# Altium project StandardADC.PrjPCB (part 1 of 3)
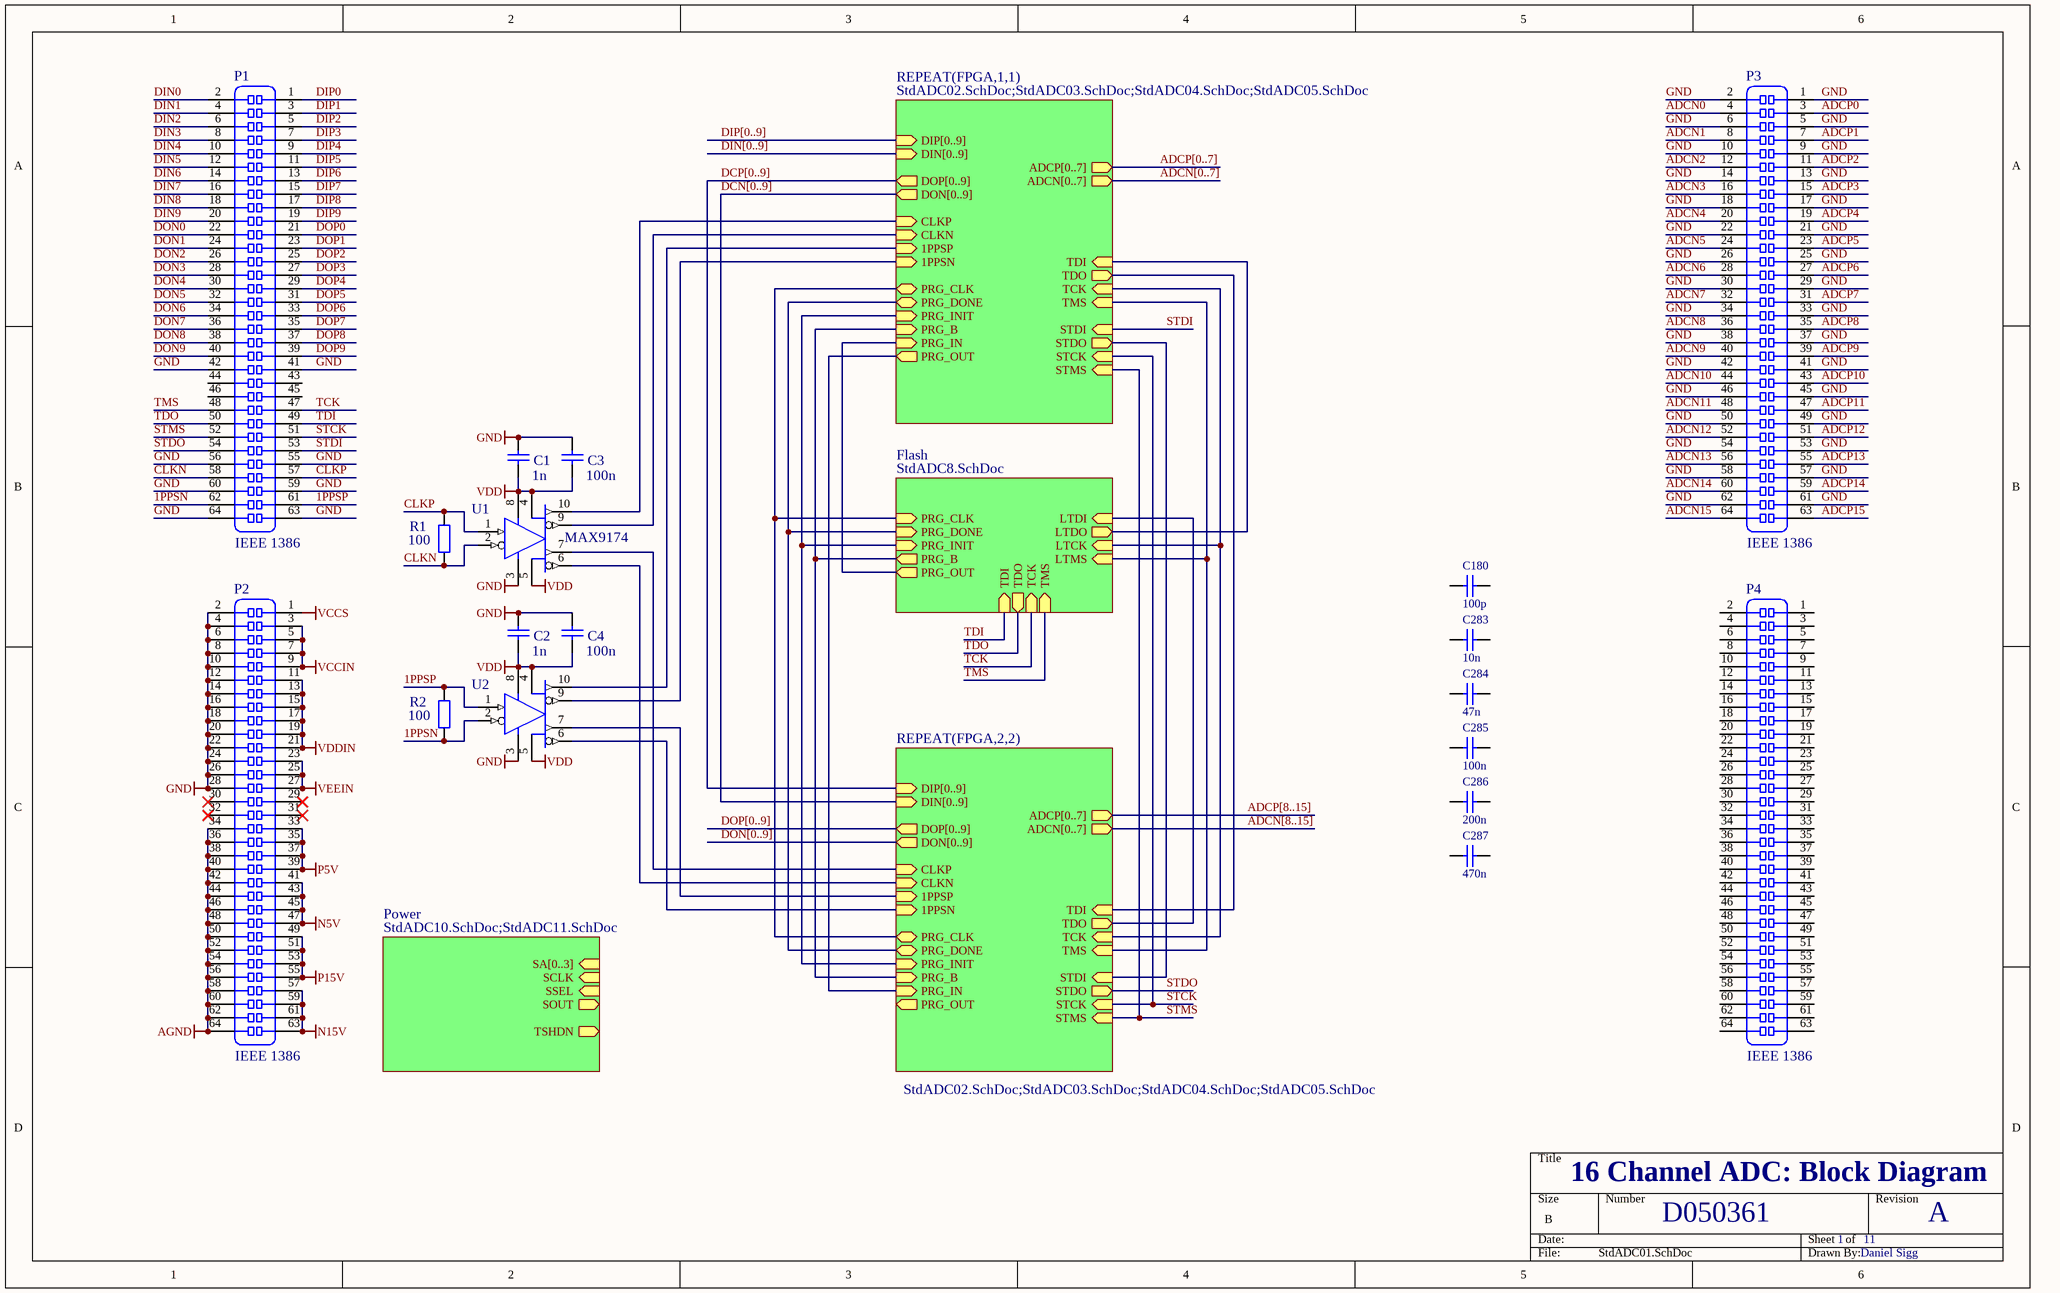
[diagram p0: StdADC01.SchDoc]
11 sheets, 2209 parts. Net scope: hierarchical (ports join the sheet entries above them; power ports are global).
Sheets:
  StdADC01.SchDoc
    FPGA1 = StdADC02.SchDoc
      ADC1 = StdADC06.SchDoc
      ADC1 = StdADC07.SchDoc
      ADC2 = StdADC06.SchDoc
      ADC2 = StdADC07.SchDoc
      ADC3 = StdADC06.SchDoc
      ADC3 = StdADC07.SchDoc
      ADC4 = StdADC06.SchDoc
      ADC4 = StdADC07.SchDoc
      ADC5 = StdADC06.SchDoc
      ADC5 = StdADC07.SchDoc
      ADC6 = StdADC06.SchDoc
      ADC6 = StdADC07.SchDoc
      ADC7 = StdADC06.SchDoc
      ADC7 = StdADC07.SchDoc
      ADC8 = StdADC06.SchDoc
      ADC8 = StdADC07.SchDoc
      DAC = StdADC09.SchDoc
    FPGA1 = StdADC03.SchDoc
    FPGA1 = StdADC04.SchDoc
    FPGA1 = StdADC05.SchDoc
    FPGA2 = StdADC02.SchDoc
      ADC1 = StdADC06.SchDoc
      ADC1 = StdADC07.SchDoc
      ADC2 = StdADC06.SchDoc
      ADC2 = StdADC07.SchDoc
      ADC3 = StdADC06.SchDoc
      ADC3 = StdADC07.SchDoc
      ADC4 = StdADC06.SchDoc
      ADC4 = StdADC07.SchDoc
      ADC5 = StdADC06.SchDoc
      ADC5 = StdADC07.SchDoc
      ADC6 = StdADC06.SchDoc
      ADC6 = StdADC07.SchDoc
      ADC7 = StdADC06.SchDoc
      ADC7 = StdADC07.SchDoc
      ADC8 = StdADC06.SchDoc
      ADC8 = StdADC07.SchDoc
      DAC = StdADC09.SchDoc
    FPGA2 = StdADC03.SchDoc
    FPGA2 = StdADC04.SchDoc
    FPGA2 = StdADC05.SchDoc
    Power = StdADC10.SchDoc
    Power = StdADC11.SchDoc
  StdADC08.SchDoc

## Sheet StdADC01.SchDoc
size B; PageSetup: Record=PageOptions|CenterHorizontal=True|CenterVertical=True|PrintScale=0.77|XCorrection=1.00|YCorrection=1.00|PrintKind=0|BorderSize=5000000|LeftOffset=0|BottomOffset=0|Orientation=2|PaperLength=1000|PaperWidth=1000|Scale=100|PaperSource=15|PrintQuality=600|MediaType=1|DitherType=10|PaperKind=11x17|PrintScaleMode=1

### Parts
C1  value 1n  [CC1005-0402]  (hidden comment: Cap)
C2  value 1n  [CC1005-0402]  (hidden comment: Cap)
C3  value 100n  [CC1608-0603]  (hidden comment: Cap)
C4  value 100n  [CC1608-0603]  (hidden comment: Cap)
C180  100p  [ECQPZ085045-5.0]
C283  10n  [ECQPZ120060-5.0]
C284  47n  [ECQPZ145065-5.0]
C285  100n  [ECQPZ170080-7.5]
C286  200n  [ECQPZ200100-10.0]
C287  470n  [ECQPZ225115-12.5]
P1  IEEE 1386  [IEEE1386_64_PLUG]
P2  IEEE 1386  [IEEE1386_64_PLUG]
P3  IEEE 1386  [IEEE1386_64_PLUG]
P4  IEEE 1386  [IEEE1386_64_PLUG]
R1  100  [CR2012-0805]
R2  100  [CR2012-0805]
U1  MAX9174  [UMAX10]
U2  MAX9174  [UMAX10]  (value not drawn)

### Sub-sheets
Flash = StdADC8.SchDoc (file not in this document): PRG_CLK (in), PRG_DONE (in), PRG_INIT (in), PRG_B (out), PRG_OUT (out), LTDI (in), LTDO (out), LTCK (in), LTMS (in), TDI (in), TDO (out), TCK (in), TMS (in)
Power = StdADC10.SchDoc;StdADC11.SchDoc: SA[0..3] (in), SCLK (in), SSEL (in), SOUT (out), TSHDN (out)
REPEAT(FPGA,1,1) = StdADC02.SchDoc;StdADC03.SchDoc;StdADC04.SchDoc;StdADC05.SchDoc: ADCP[0..7] (out), ADCN[0..7] (out), DIP[0..9] (in), DOP[0..9] (out), DIN[0..9] (in), DON[0..9] (out), CLKP (in), CLKN (in), PRG_CLK (bidir), PRG_DONE (bidir), PRG_INIT (in), PRG_B (in), PRG_IN (in), PRG_OUT (out), TDI (in), TDO (out), TCK (in), TMS (in), STDI (in), STDO (out), STCK (in), STMS (in), 1PPSP (in), 1PPSN (in)
REPEAT(FPGA,2,2) = StdADC02.SchDoc;StdADC03.SchDoc;StdADC04.SchDoc;StdADC05.SchDoc: ADCP[0..7] (out), ADCN[0..7] (out), DIP[0..9] (in), DOP[0..9] (out), DIN[0..9] (in), DON[0..9] (out), PRG_CLK (bidir), PRG_DONE (bidir), PRG_INIT (in), PRG_B (in), PRG_IN (in), PRG_OUT (out), TDI (in), TDO (out), TCK (in), TMS (in), STDI (in), STDO (out), STCK (in), STMS (in), CLKP (in), CLKN (in), 1PPSP (in), 1PPSN (in)

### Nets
AGND: P2.34 P2.36 P2.38 P2.40 P2.42 P2.44 P2.46 P2.48 P2.50 P2.52 P2.54 P2.56 P2.58 P2.60 P2.62 P2.64
GND: C1.1 C2.1 C3.1 C4.1 P1.41 P1.42 P1.55 P1.56 P1.59 P1.60 P1.63 P1.64 P2.2 P2.4 P2.6 P2.8 P2.10 P2.12 P2.14 P2.16 P2.18 P2.20 P2.22 P2.24 P2.26 P2.28 P3.1 P3.2 P3.5 P3.6 P3.9 P3.10 P3.13 P3.14 P3.17 P3.18 P3.21 P3.22 P3.25 P3.26 P3.29 P3.30 P3.33 P3.34 P3.37 P3.38 P3.41 P3.42 P3.45 P3.46 P3.49 P3.50 P3.53 P3.54 P3.57 P3.58 P3.61 P3.62 U1.3(GND) U2.3(GND)
N5V: P2.41 P2.43 P2.45 P2.47
N15V: P2.57 P2.59 P2.61 P2.63
P5V: P2.33 P2.35 P2.37 P2.39
P15V: P2.49 P2.51 P2.53 P2.55
VCCIN: P2.3 P2.5 P2.7 P2.9
VCCS: P2.1
VDD: C1.2 C2.2 C3.2 C4.2 U1.4(~{PD1}) U1.5(~{PD0}) U1.8(VCC) U2.4(~{PD1}) U2.5(~{PD0}) U2.8(VCC)
VDDIN: P2.11 P2.13 P2.15 P2.17 P2.19 P2.21
VEEIN: P2.23 P2.25 P2.27
1PPSN: P1.62 R2.2 U2.2(IN-)
1PPSP: P1.61 R2.1 U2.1(IN+)
ADCN0: P3.4
ADCN1: P3.8
ADCN2: P3.12
ADCN3: P3.16
ADCN4: P3.20
ADCN5: P3.24
ADCN6: P3.28
ADCN7: P3.32
ADCN8: P3.36
ADCN9: P3.40
ADCN10: P3.44
ADCN11: P3.48
ADCN12: P3.52
ADCN13: P3.56
ADCN14: P3.60
ADCN15: P3.64
ADCP0: P3.3
ADCP1: P3.7
ADCP2: P3.11
ADCP3: P3.15
ADCP4: P3.19
ADCP5: P3.23
ADCP6: P3.27
ADCP7: P3.31
ADCP8: P3.35
ADCP9: P3.39
ADCP10: P3.43
ADCP11: P3.47
ADCP12: P3.51
ADCP13: P3.55
ADCP14: P3.59
ADCP15: P3.63
CLKN: P1.58 R1.2 U1.2(IN-)
CLKP: P1.57 R1.1 U1.1(IN+)
DIN0: P1.2
DIN1: P1.4
DIN2: P1.6
DIN3: P1.8
DIN4: P1.10
DIN5: P1.12
DIN6: P1.14
DIN7: P1.16
DIN8: P1.18
DIN9: P1.20
DIP0: P1.1
DIP1: P1.3
DIP2: P1.5
DIP3: P1.7
DIP4: P1.9
DIP5: P1.11
DIP6: P1.13
DIP7: P1.15
DIP8: P1.17
DIP9: P1.19
DON0: P1.22
DON1: P1.24
DON2: P1.26
DON3: P1.28
DON4: P1.30
DON5: P1.32
DON6: P1.34
DON7: P1.36
DON8: P1.38
DON9: P1.40
DOP0: P1.21
DOP1: P1.23
DOP2: P1.25
DOP3: P1.27
DOP4: P1.29
DOP5: P1.31
DOP6: P1.33
DOP7: P1.35
DOP8: P1.37
DOP9: P1.39
STCK: P1.51 ; sheet REPEAT(FPGA,1,1)/STCK, sheet REPEAT(FPGA,2,2)/STCK
STDI: P1.53 ; sheet REPEAT(FPGA,1,1)/STDI
STDO: P1.54 ; sheet REPEAT(FPGA,2,2)/STDO
STMS: P1.52 ; sheet REPEAT(FPGA,1,1)/STMS, sheet REPEAT(FPGA,2,2)/STMS
TCK: P1.47 ; sheet Flash/TCK
TDI: P1.49 ; sheet Flash/TDI
TDO: P1.50 ; sheet Flash/TDO
TMS: P1.48 ; sheet Flash/TMS
NetU1_6: U1.6(OUT1-) ; sheet REPEAT(FPGA,2,2)/CLKN
NetU1_7: U1.7(OUT1+) ; sheet REPEAT(FPGA,2,2)/CLKP
NetU1_9: U1.9(OUT0-) ; sheet REPEAT(FPGA,1,1)/CLKN
NetU1_10: U1.10(OUT0+) ; sheet REPEAT(FPGA,1,1)/CLKP
NetU2_6: U2.6(OUT1-) ; sheet REPEAT(FPGA,2,2)/1PPSN
NetU2_7: U2.7(OUT1+) ; sheet REPEAT(FPGA,2,2)/1PPSP
NetU2_9: U2.9(OUT0-) ; sheet REPEAT(FPGA,1,1)/1PPSN
NetU2_10: U2.10(OUT0+) ; sheet REPEAT(FPGA,1,1)/1PPSP
NetU4A#1_AA14: sheet REPEAT(FPGA,1,1)/PRG_IN, sheet Flash/PRG_OUT
NetU4A#1_W12: sheet REPEAT(FPGA,1,1)/PRG_INIT, sheet REPEAT(FPGA,2,2)/PRG_INIT, sheet Flash/PRG_INIT
NetU4A#1_Y1: sheet REPEAT(FPGA,1,1)/STDO, sheet REPEAT(FPGA,2,2)/STDI
NetU4A#1_Y12: sheet REPEAT(FPGA,1,1)/PRG_OUT, sheet REPEAT(FPGA,2,2)/PRG_IN
NetU4A#3_A2: sheet REPEAT(FPGA,1,1)/PRG_B, sheet REPEAT(FPGA,2,2)/PRG_B, sheet Flash/PRG_B
NetU4A#3_A20: sheet REPEAT(FPGA,1,1)/TMS, sheet REPEAT(FPGA,2,2)/TMS, sheet Flash/LTMS
NetU4A#3_A21: sheet REPEAT(FPGA,1,1)/TCK, sheet REPEAT(FPGA,2,2)/TCK, sheet Flash/LTCK
NetU4A#3_AA22: sheet REPEAT(FPGA,1,1)/PRG_CLK, sheet REPEAT(FPGA,2,2)/PRG_CLK, sheet Flash/PRG_CLK
NetU4A#3_AB21: sheet REPEAT(FPGA,1,1)/PRG_DONE, sheet REPEAT(FPGA,2,2)/PRG_DONE, sheet Flash/PRG_DONE
NetU4A#3_B1: sheet REPEAT(FPGA,1,1)/TDI, sheet Flash/LTDO
NetU4A#3_B22: sheet REPEAT(FPGA,1,1)/TDO, sheet REPEAT(FPGA,2,2)/TDI
NetU4B#3_B22: sheet REPEAT(FPGA,2,2)/TDO, sheet Flash/LTDI

Not connected (* = marked no-connect by the designer): C180 1 2; C283 1 2; C284 1 2; C285 1 2; C286 1 2; C287 1 2; P1 43 44 45 46; P2 29* 30* 31* 32*; P4 1 2 3 4 5 6 7 8 9 10 11 12 13 14 15 16 17 18 19 20 21 22 23 24 25 26 27 28 29 30 31 32 33 34 35 36 37 38 39 40 41 42 43 44 45 46 47 48 49 50 51 52 53 54 55 56 57 58 59 60 61 62 63 64

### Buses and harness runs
bus ADCN[0..7] = sheet REPEAT(FPGA,1,1)/ADCN[0..7]
bus ADCN[8..15] = sheet REPEAT(FPGA,2,2)/ADCN[0..7]
bus ADCP[0..7] = sheet REPEAT(FPGA,1,1)/ADCP[0..7]
bus ADCP[8..15] = sheet REPEAT(FPGA,2,2)/ADCP[0..7]
bus DCN[0..9] = sheet REPEAT(FPGA,1,1)/DON[0..9] = sheet REPEAT(FPGA,2,2)/DIN[0..9]
bus DCP[0..9] = sheet REPEAT(FPGA,1,1)/DOP[0..9] = sheet REPEAT(FPGA,2,2)/DIP[0..9]
bus DIN[0..9] = sheet REPEAT(FPGA,1,1)/DIN[0..9]
bus DIP[0..9] = sheet REPEAT(FPGA,1,1)/DIP[0..9]
bus DON[0..9] = sheet REPEAT(FPGA,2,2)/DON[0..9]
bus DOP[0..9] = sheet REPEAT(FPGA,2,2)/DOP[0..9]

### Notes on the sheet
- 16 Channel ADC: Block Diagram
- D050361
- 1
- 11
- A
- Daniel Sigg

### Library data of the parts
C1-C4 = Cap: Capacitor; Manufacturer: Generic Components; Part Number: 399-1254-1-ND; Class I: Passive
C180 C283-C287 = PolyCap: Polypropylene Film Capacitor, radial lead; Tolerance: 2%; Voltage Rating: 50V
P1-P4 = IEEE_1386_PLUG_64: Mezzanine card connector, 64 pin, plug, IEEE 1386
R1 R2 = Res2: Resistor
U1 U2 = MAX9174: LVDS to LVDS 1:2 splitter

## Sheet StdADC02.SchDoc
size B
Used 2 times, as channels FPGA1, FPGA2. Parts and nets are listed once, with the designators drawn on the sheet.
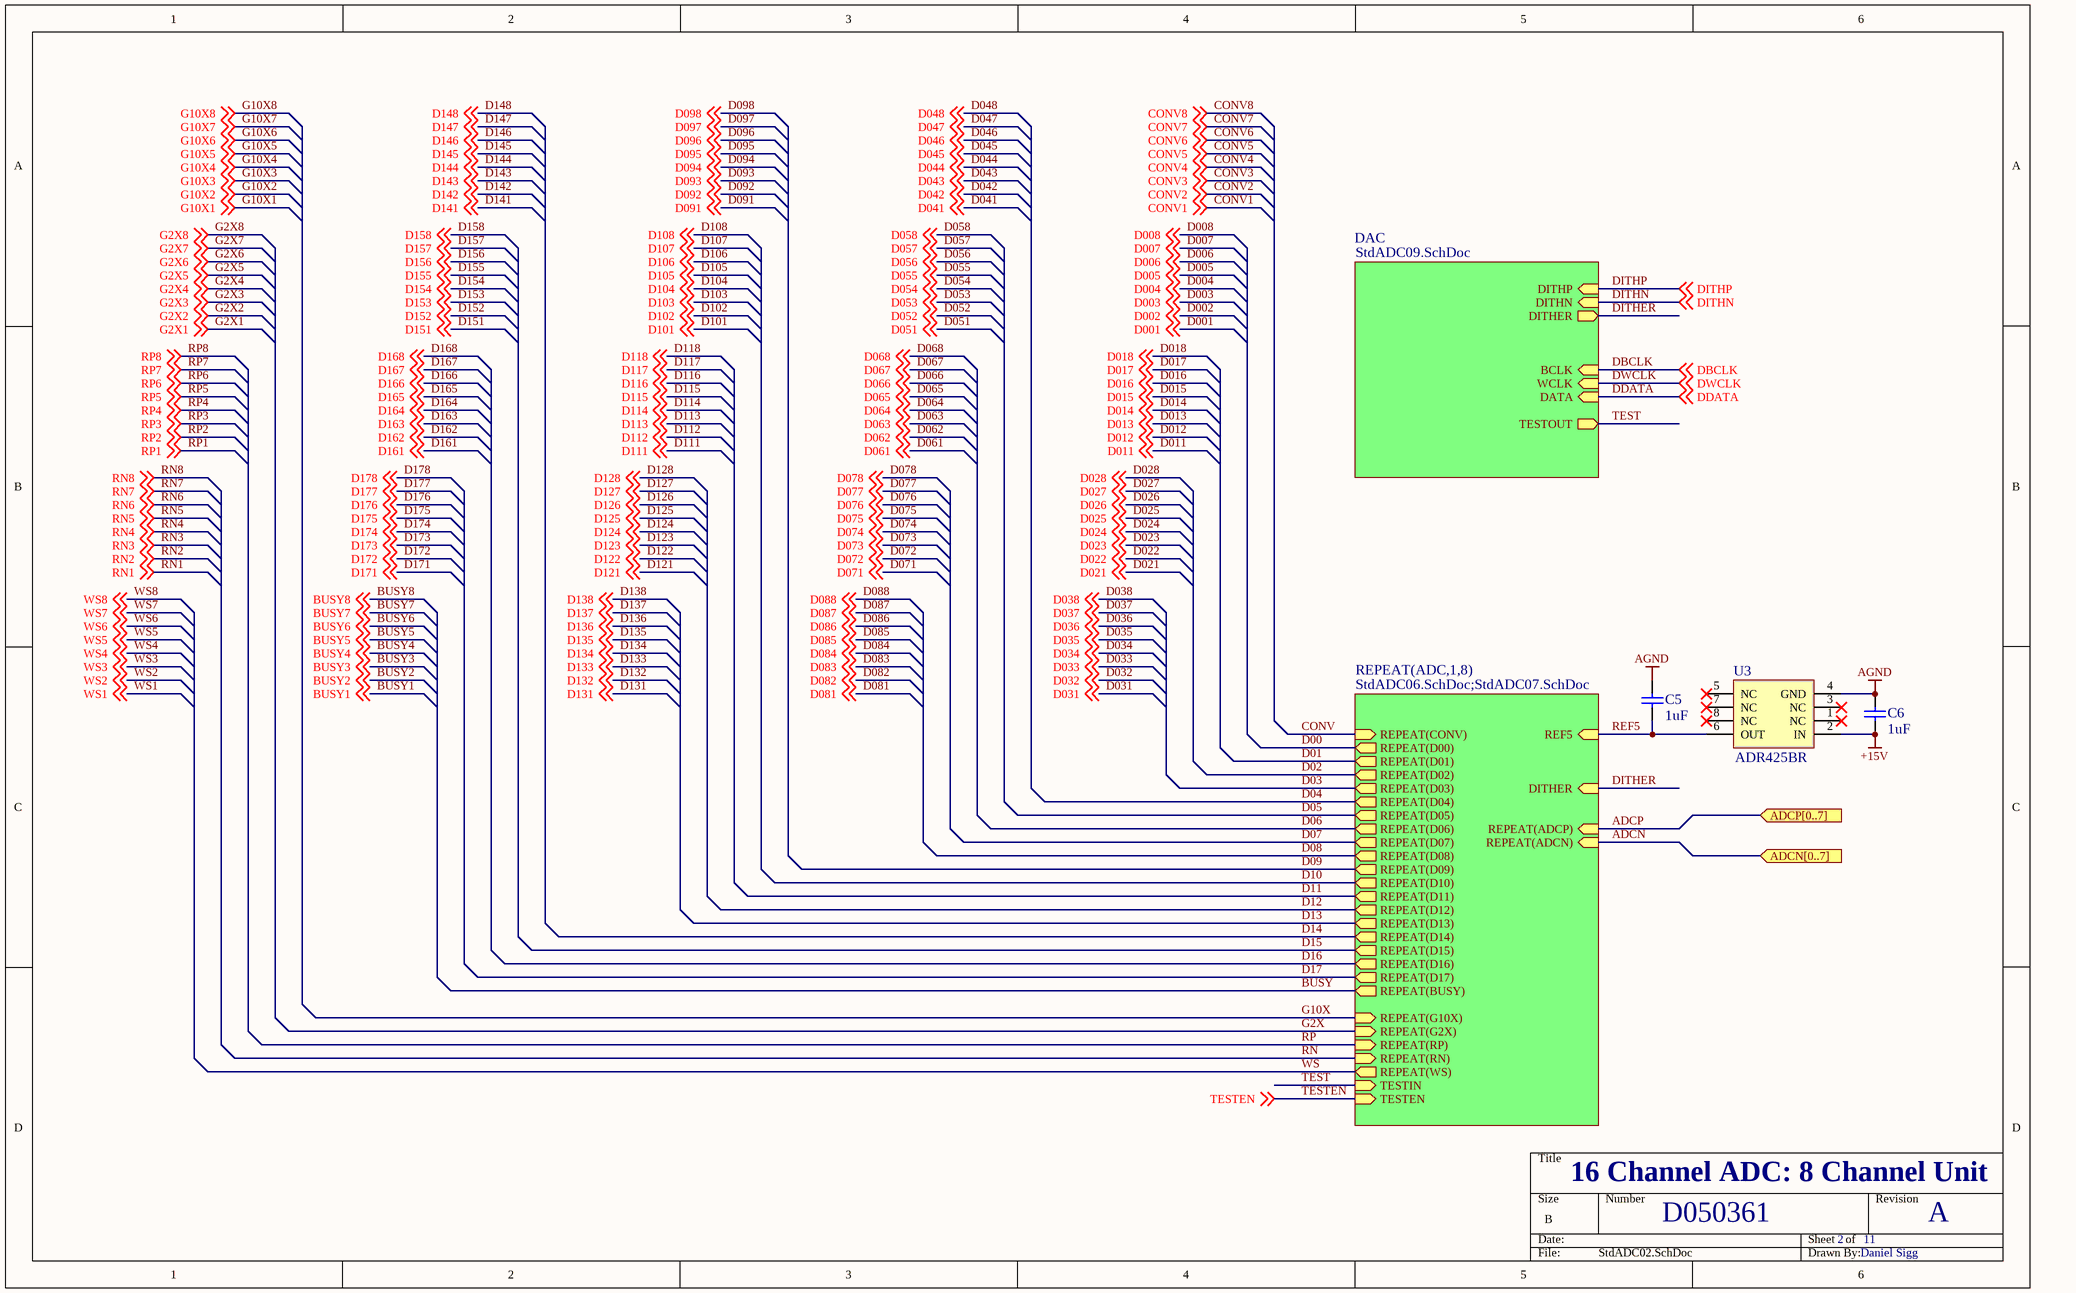
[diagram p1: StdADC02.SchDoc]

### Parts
C5  1uF  [CC2012-0805]
C6  1uF  [CC2012-0805]
U3  ADR425BR  [R-8]

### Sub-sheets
DAC = StdADC09.SchDoc: TESTOUT (out), BCLK (in), WCLK (in), DATA (in), DITHP (in), DITHN (in), DITHER (out)
REPEAT(ADC,1,8) = StdADC06.SchDoc;StdADC07.SchDoc: REPEAT(D00) (out), REPEAT(ADCP) (in), REPEAT(ADCN) (in), REPEAT(CONV) (in), REPEAT(D10) (out), REPEAT(D04) (out), REPEAT(D05) (out), REPEAT(D03) (out), REPEAT(D01) (out), REPEAT(D02) (out), REPEAT(D06) (out), REPEAT(D07) (out), REPEAT(D08) (out), REPEAT(D09) (out), REPEAT(D11) (out), REPEAT(D12) (out), REPEAT(D13) (out), REPEAT(D14) (out), REPEAT(D15) (out), REPEAT(D16) (out), REPEAT(BUSY) (out), REPEAT(D17) (out), REF5 (in), REPEAT(G2X) (in), REPEAT(G10X) (in), REPEAT(RP) (in), REPEAT(WS) (out), TESTIN (in), TESTEN (in), REPEAT(RN) (in), DITHER (in)

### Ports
ADCN[0..7] (in), ADCP[0..7] (in)

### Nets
+15V: C6.2 U3.2(IN)
AGND: C5.1 C6.1 U3.4(GND)
DBCLK: off-sheet DBCLK, sheet DAC/BCLK
DDATA: off-sheet DDATA, sheet DAC/DATA
DITHER: sheet REPEAT(ADC,1,8)/DITHER, sheet DAC/DITHER
DITHN: off-sheet DITHN, sheet DAC/DITHN
DITHP: off-sheet DITHP, sheet DAC/DITHP
DWCLK: off-sheet DWCLK, sheet DAC/WCLK
REF5: C5.2 U3.6(OUT) ; sheet REPEAT(ADC,1,8)/REF5
TEST: sheet REPEAT(ADC,1,8)/TESTIN, sheet DAC/TESTOUT
TESTEN: off-sheet TESTEN, sheet REPEAT(ADC,1,8)/TESTEN

Not connected (* = marked no-connect by the designer): U3 1(NC)* 3(NC)* 5(NC)* 7(NC)* 8(NC)*

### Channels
FPGA1: designators end in A
FPGA2: designators end in B

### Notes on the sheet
- 16 Channel ADC: 8 Channel Unit
- D050361
- 2
- 11
- A
- Daniel Sigg

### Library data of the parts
C5 C6 = Cap Semi: Capacitor (Semiconductor SIM Model)
U3 = ADR292ER: Low-Noise Micropower Precision Voltage Reference; Note: Pins 1, 3, 5, 7 and 8 are not connected

## Sheet StdADC06.SchDoc
size B
Used 16 times, as channels FPGA1/ADC1, FPGA1/ADC2, FPGA1/ADC3, FPGA1/ADC4, FPGA1/ADC5, FPGA1/ADC6, FPGA1/ADC7, FPGA1/ADC8, FPGA2/ADC1, FPGA2/ADC2, FPGA2/ADC3, FPGA2/ADC4, FPGA2/ADC5, FPGA2/ADC6, FPGA2/ADC7, FPGA2/ADC8. Parts and nets are listed once, with the designators drawn on the sheet.
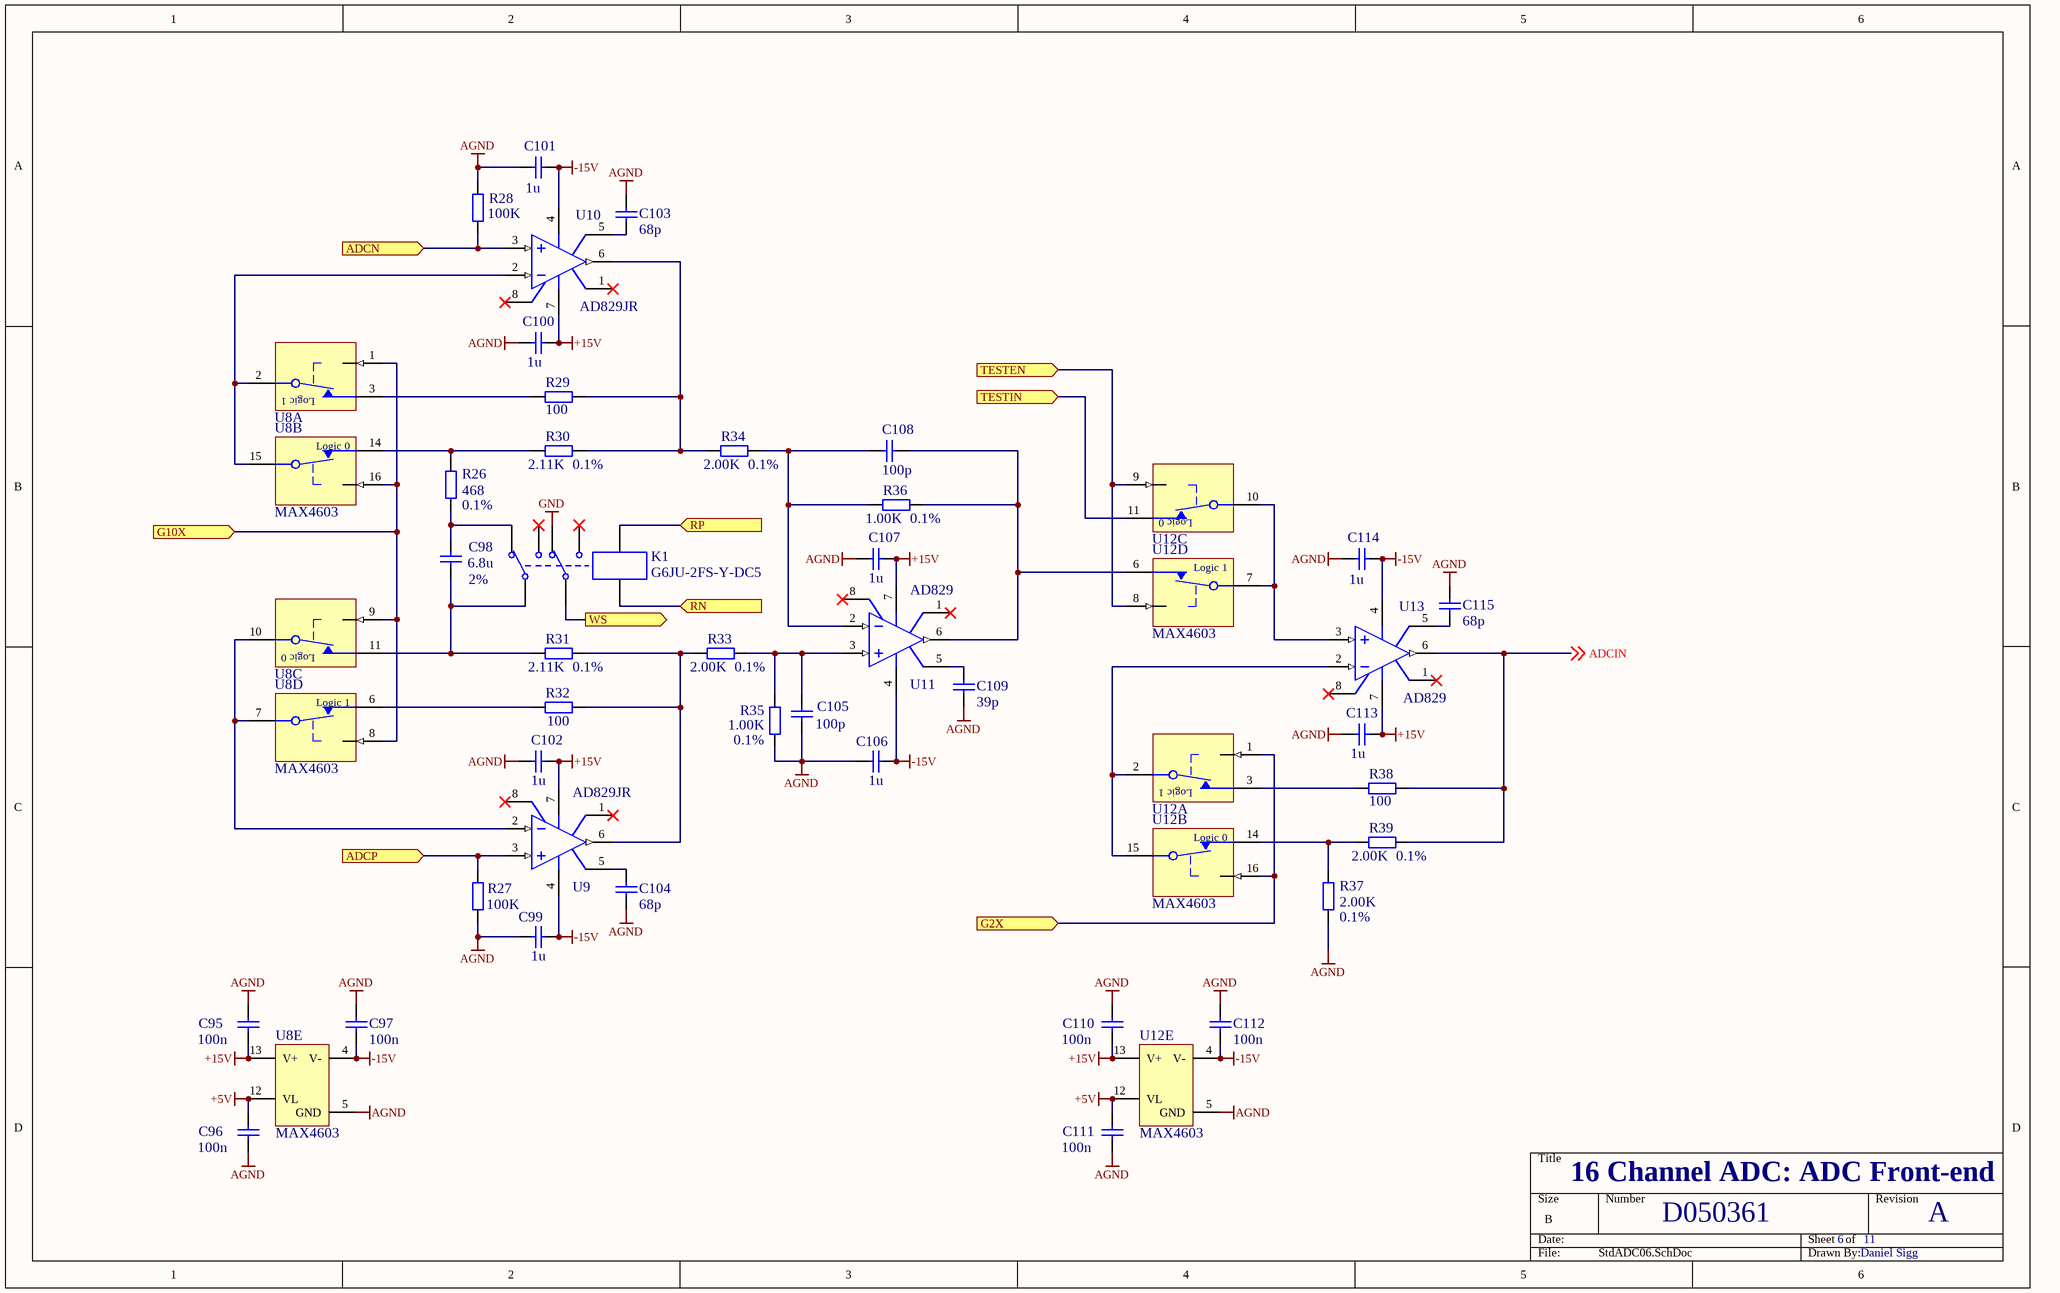
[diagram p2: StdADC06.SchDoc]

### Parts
C95  100n  [CC2012-0805]
C96  100n  [CC2012-0805]
C97  100n  [CC2012-0805]
C98  Tolerance: 2%  [CC2012-0805]  (hidden comment: 6.8u)
C99  1u  [CC2012-0805]
C100  1u  [CC2012-0805]
C101  1u  [CC2012-0805]
C102  1u  [CC2012-0805]
C103  68p  [CC2012-0805]
C104  68p  [CC2012-0805]
C105  100p  [CC2012-0805]
C106  1u  [CC2012-0805]
C107  1u  [CC2012-0805]
C108  100p  [CC2012-0805]
C109  39p  [CC2012-0805]
C110  100n  [CC2012-0805]
C111  100n  [CC2012-0805]
C112  100n  [CC2012-0805]
C113  1u  [CC2012-0805]
C114  1u  [CC2012-0805]
C115  68p  [CC2012-0805]
K1  G6JU-2FS-Y-DC5  [DIP-P8/E10]
R26  Tolerance: 0.1%  [CR2012-0805]  (hidden comment: 468)
R27  100K  [CR2012-0805]
R28  100K  [CR2012-0805]
R29  100  [CR2012-0805]
R30  Tolerance: 0.1%  [CR2012-0805]  (hidden comment: 2.11K)
R31  Tolerance: 0.1%  [CR2012-0805]  (hidden comment: 2.11K)
R32  100  [CR2012-0805]
R33  Tolerance: 0.1%  [CR2012-0805]  (hidden comment: 2.00K)
R34  Tolerance: 0.1%  [CR2012-0805]  (hidden comment: 2.00K)
R35  Tolerance: 0.1%  [CR2012-0805]  (hidden comment: 1.00K)
R36  Tolerance: 0.1%  [CR2012-0805]  (hidden comment: 1.00K)
R37  Tolerance: 0.1%  [CR2012-0805]  (hidden comment: 2.00K)
R38  100  [CR2012-0805]
R39  Tolerance: 0.1%  [CR2012-0805]  (hidden comment: 2.00K)
U8  MAX4603  [SSO-G16/X.4]  (value not drawn)  (parts A,B,C,D,E of 5)
U9  AD829JR  [R-8D]
U10  AD829JR  [R-8D]
U11  AD829  [R-8D]
U12  MAX4603  [SSO-G16/X.4]  (value not drawn)  (parts A,B,C,D,E of 5)
U13  AD829  [R-8D]

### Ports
ADCN (in), ADCP (in), G2X (in), G10X (in), RN (in), RP (in), TESTEN (in), TESTIN (in), WS (out)

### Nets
+5V: C96.1 C111.1 U8.12(VL) U12.12(VL)
+15V: C95.2 C100.1 C102.1 C107.1 C110.2 C113.1 U8.13(V+) U9.7(V+) U10.7(V+) U11.7(V+) U12.13(V+) U13.7(V+)
-15V: C97.2 C99.1 C101.1 C106.1 C112.2 C114.1 U8.4(V-) U9.4(V-) U10.4(V-) U11.4(V-) U12.4(V-) U13.4(V-)
AGND: C95.1 C96.2 C97.1 C99.2 C100.2 C101.2 C102.2 C103.2 C104.2 C105.2 C106.2 C107.2 C109.2 C110.1 C111.2 C112.1 C113.2 C114.2 C115.2 R27.2 R28.2 R35.2 R37.2 U8.5(GND) U12.5(GND)
GND: K1.5
ADCIN: R38.1 R39.1 U13.6(OUT) ; off-sheet ADCIN
ADCN: R28.1 U10.3(IN+) ; port ADCN
ADCP: R27.1 U9.3(IN+) ; port ADCP
G2X: U12.1(IN1) U12.16(IN2) ; port G2X
G10X: U8.1(IN1) U8.8(IN4) U8.9(IN3) U8.16(IN2) ; port G10X
RN: K1.7 ; port RN
RP: K1.8 ; port RP
TESTEN: U12.8(IN4) U12.9(IN3) ; port TESTEN
TESTIN: U12.11(NC3) ; port TESTIN
WS: K1.4 ; port WS
NetC98_1: C98.1 K1.2 R26.2
NetC98_2: C98.2 K1.1 R31.2 U8.11(NC3)
NetC103_1: C103.1 U10.5(C_COMP)
NetC104_1: C104.1 U9.5(C_COMP)
NetC105_1: C105.1 R33.1 R35.1 U11.3(IN+)
NetC108_1: C108.1 R36.1 U11.6(OUT) U12.6(NO4)
NetC108_2: C108.2 R34.1 R36.2 U11.2(IN-)
NetC109_1: C109.1 U11.5(C_COMP)
NetC115_1: C115.1 U13.5(C_COMP)
NetR26_1: R26.1 R30.2 U8.14(NC2)
NetR29_1: R29.1 R30.1 R34.2 U10.6(OUT)
NetR29_2: R29.2 U8.3(NO1)
NetR31_1: R31.1 R32.1 R33.2 U9.6(OUT)
NetR32_2: R32.2 U8.6(NO4)
NetR37_1: R37.1 R39.2 U12.14(NC2)
NetR38_2: R38.2 U12.3(NO1)
NetU8_2: U8.2(COM1) U8.15(COM2) U10.2(IN-)
NetU8_7: U8.7(COM4) U8.10(COM3) U9.2(IN-)
NetU12_2: U12.2(COM1) U12.15(COM2) U13.2(IN-)
NetU12_7: U12.7(COM4) U12.10(COM3) U13.3(IN+)

Not connected (* = marked no-connect by the designer): K1 3* 6*; U9 1(OS_NUL)* 8(OS_NUL)*; U10 1(OS_NUL)* 8(OS_NUL)*; U11 1(OS_NUL)* 8(OS_NUL)*; U13 1(OS_NUL)* 8(OS_NUL)*

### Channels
FPGA1/ADC1: designators end in A; ports ADCN=ADCN1_FPGA1 ADCP=ADCP1_FPGA1 G2X=G2X1 G10X=G10X1 RN=RN1 RP=RP1 TESTEN=TESTEN TESTIN=TEST_FPGA1 WS=WS1
FPGA1/ADC2: designators end in B; ports ADCN=ADCN2_FPGA1 ADCP=ADCP2_FPGA1 G2X=G2X2 G10X=G10X2 RN=RN2 RP=RP2 TESTEN=TESTEN TESTIN=TEST_FPGA1 WS=WS2
FPGA1/ADC3: designators end in C; ports ADCN=ADCN3_FPGA1 ADCP=ADCP3_FPGA1 G2X=G2X3 G10X=G10X3 RN=RN3 RP=RP3 TESTEN=TESTEN TESTIN=TEST_FPGA1 WS=WS3
FPGA1/ADC4: designators end in D; ports ADCN=ADCN4_FPGA1 ADCP=ADCP4_FPGA1 G2X=G2X4 G10X=G10X4 RN=RN4 RP=RP4 TESTEN=TESTEN TESTIN=TEST_FPGA1 WS=WS4
FPGA1/ADC5: designators end in E; ports ADCN=ADCN5_FPGA1 ADCP=ADCP5_FPGA1 G2X=G2X5 G10X=G10X5 RN=RN5 RP=RP5 TESTEN=TESTEN TESTIN=TEST_FPGA1 WS=WS5
FPGA1/ADC6: designators end in F; ports ADCN=ADCN6_FPGA1 ADCP=ADCP6_FPGA1 G2X=G2X6 G10X=G10X6 RN=RN6 RP=RP6 TESTEN=TESTEN TESTIN=TEST_FPGA1 WS=WS6
FPGA1/ADC7: designators end in G; ports ADCN=ADCN7_FPGA1 ADCP=ADCP7_FPGA1 G2X=G2X7 G10X=G10X7 RN=RN7 RP=RP7 TESTEN=TESTEN TESTIN=TEST_FPGA1 WS=WS7
FPGA1/ADC8: designators end in H; ports ADCN=ADCN8_FPGA1 ADCP=ADCP8_FPGA1 G2X=G2X8 G10X=G10X8 RN=RN8 RP=RP8 TESTEN=TESTEN TESTIN=TEST_FPGA1 WS=WS8
FPGA2/ADC1: designators end in I; ports ADCN=ADCN1_FPGA2 ADCP=ADCP1_FPGA2 G2X=G2X1 G10X=G10X1 RN=RN1 RP=RP1 TESTEN=TESTEN TESTIN=TEST_FPGA2 WS=WS1
FPGA2/ADC2: designators end in J; ports ADCN=ADCN2_FPGA2 ADCP=ADCP2_FPGA2 G2X=G2X2 G10X=G10X2 RN=RN2 RP=RP2 TESTEN=TESTEN TESTIN=TEST_FPGA2 WS=WS2
FPGA2/ADC3: designators end in K; ports ADCN=ADCN3_FPGA2 ADCP=ADCP3_FPGA2 G2X=G2X3 G10X=G10X3 RN=RN3 RP=RP3 TESTEN=TESTEN TESTIN=TEST_FPGA2 WS=WS3
FPGA2/ADC4: designators end in L; ports ADCN=ADCN4_FPGA2 ADCP=ADCP4_FPGA2 G2X=G2X4 G10X=G10X4 RN=RN4 RP=RP4 TESTEN=TESTEN TESTIN=TEST_FPGA2 WS=WS4
FPGA2/ADC5: designators end in M; ports ADCN=ADCN5_FPGA2 ADCP=ADCP5_FPGA2 G2X=G2X5 G10X=G10X5 RN=RN5 RP=RP5 TESTEN=TESTEN TESTIN=TEST_FPGA2 WS=WS5
FPGA2/ADC6: designators end in N; ports ADCN=ADCN6_FPGA2 ADCP=ADCP6_FPGA2 G2X=G2X6 G10X=G10X6 RN=RN6 RP=RP6 TESTEN=TESTEN TESTIN=TEST_FPGA2 WS=WS6
FPGA2/ADC7: designators end in O; ports ADCN=ADCN7_FPGA2 ADCP=ADCP7_FPGA2 G2X=G2X7 G10X=G10X7 RN=RN7 RP=RP7 TESTEN=TESTEN TESTIN=TEST_FPGA2 WS=WS7
FPGA2/ADC8: designators end in P; ports ADCN=ADCN8_FPGA2 ADCP=ADCP8_FPGA2 G2X=G2X8 G10X=G10X8 RN=RN8 RP=RP8 TESTEN=TESTEN TESTIN=TEST_FPGA2 WS=WS8

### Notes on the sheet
- 16 Channel ADC: ADC Front-end
- D050361
- 6
- 11
- A
- Daniel Sigg

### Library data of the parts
C95-C115 = Cap Semi: Capacitor (Semiconductor SIM Model)
K1 = Relay-DPDT: Dual-Pole Dual-Throw Relay
R26 R30 R31 R33-R37 R39 = Res2: Resistor
R27-R29 R32 R38 = Res2: Resistor; Tolerance: 1%
U8 U12 = MAX4603: Quad SPST analog switch, NC/NO
U9-U11 U13 = AD829JR: High-Speed, Low-Noise Video Operational Amplifier; PackageDocument: 1998

## Sheet StdADC07.SchDoc
size B
Used 16 times, as channels FPGA1/ADC1, FPGA1/ADC2, FPGA1/ADC3, FPGA1/ADC4, FPGA1/ADC5, FPGA1/ADC6, FPGA1/ADC7, FPGA1/ADC8, FPGA2/ADC1, FPGA2/ADC2, FPGA2/ADC3, FPGA2/ADC4, FPGA2/ADC5, FPGA2/ADC6, FPGA2/ADC7, FPGA2/ADC8. Parts and nets are listed once, with the designators drawn on the sheet.
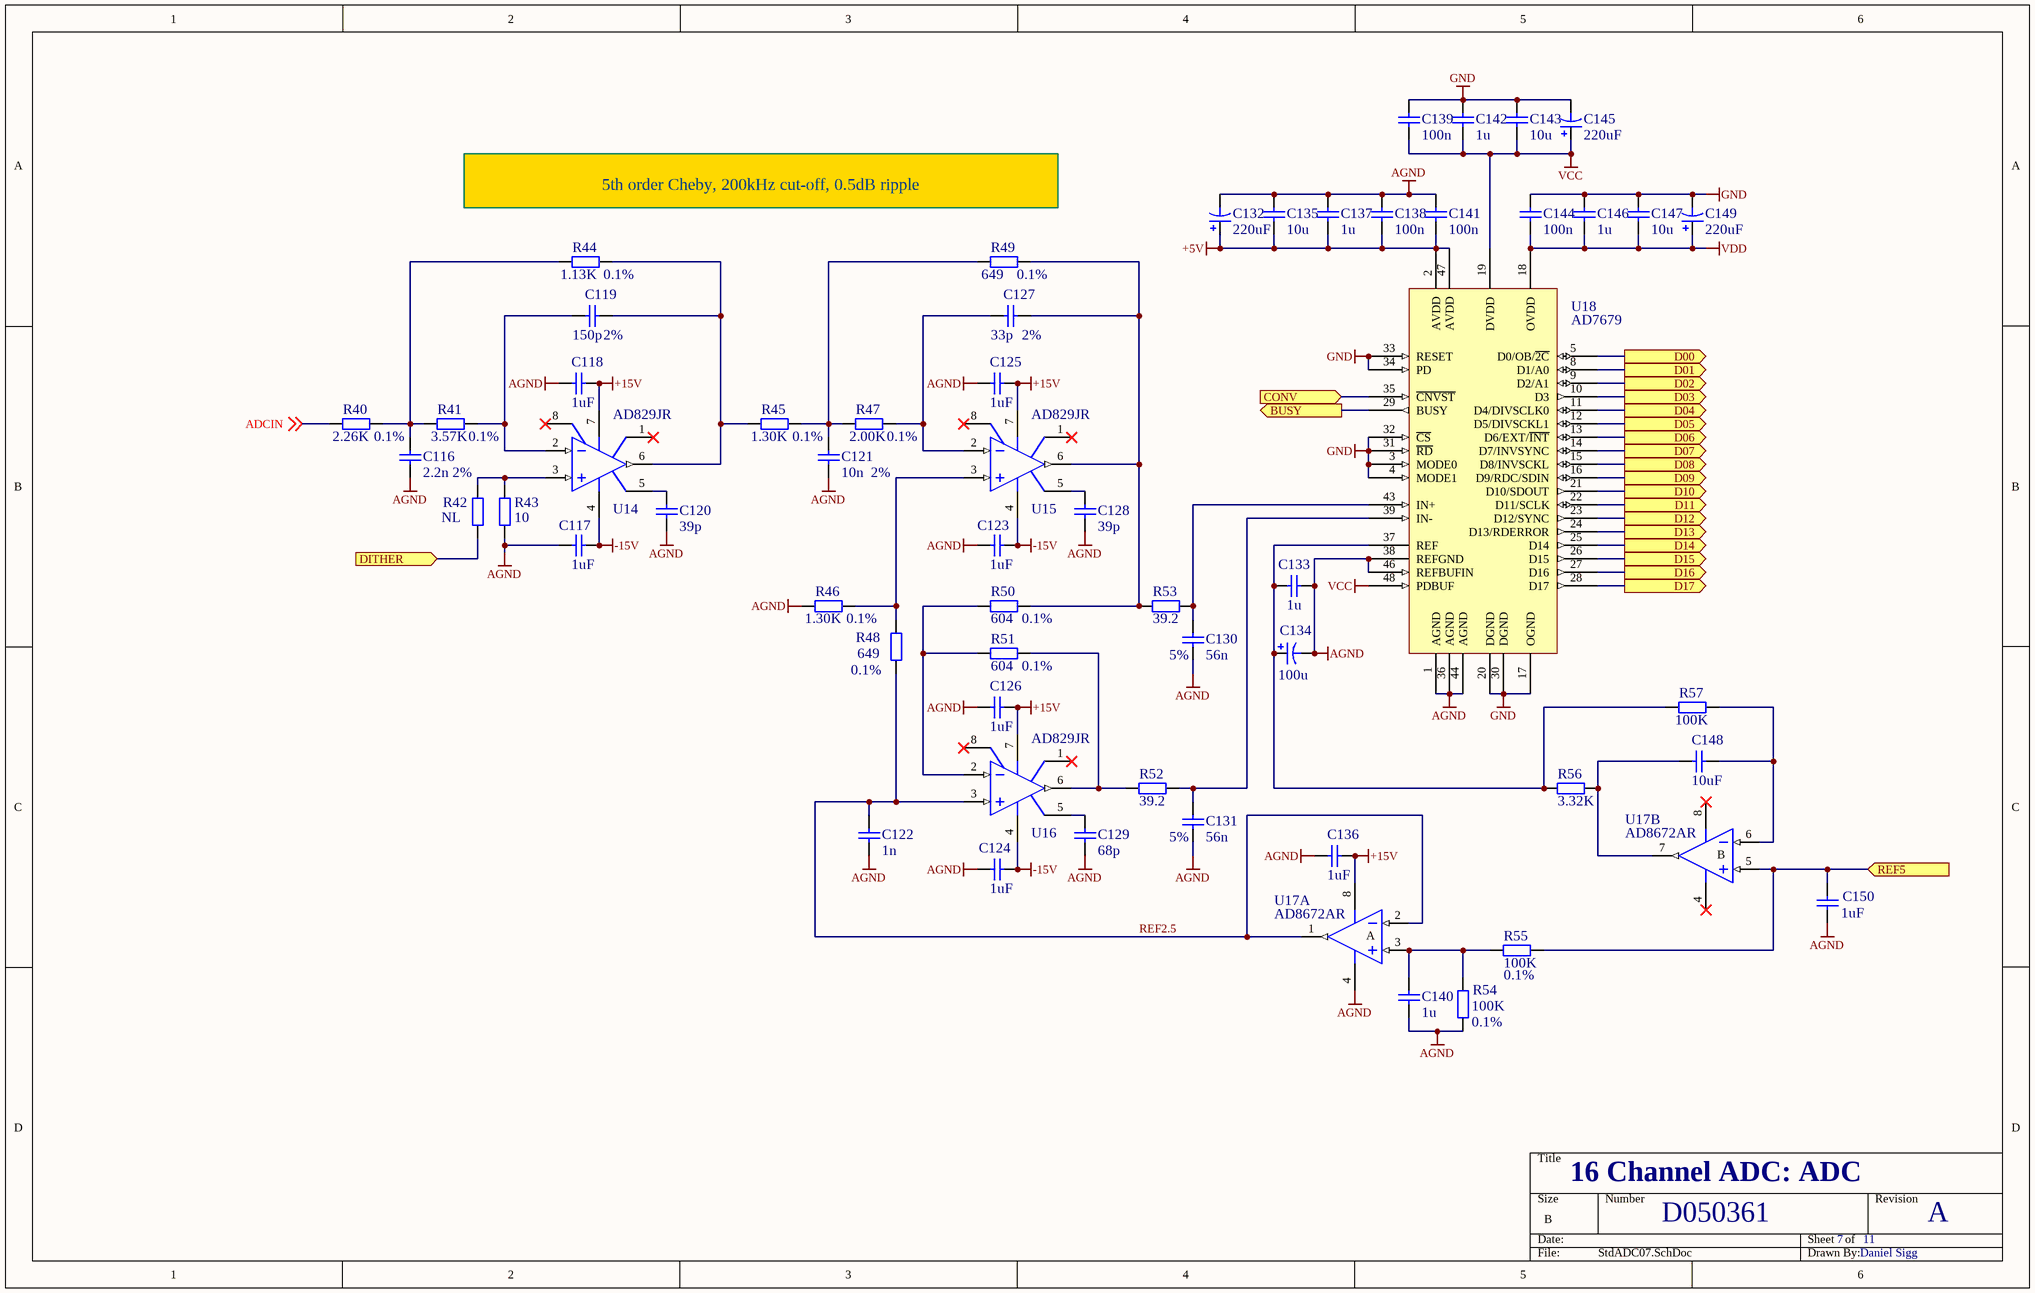
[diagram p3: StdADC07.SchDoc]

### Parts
C116  Tolerance: 2%  [CC2012-0805]  (hidden comment: 2.2n)
C117  1uF  [CC2012-0805]
C118  1uF  [CC2012-0805]
C119  Tolerance: 2%  [CC2012-0805]  (hidden comment: 150p)
C120  39p  [CC2012-0805]
C121  Tolerance: 2%  [CC2012-0805]  (hidden comment: 10n)
C122  1n  [CC2012-0805]
C123  1uF  [CC2012-0805]
C124  1uF  [CC2012-0805]
C125  1uF  [CC2012-0805]
C126  1uF  [CC2012-0805]
C127  Tolerance: 2%  [CC2012-0805]  (hidden comment: 33p)
C128  39p  [CC2012-0805]
C129  68p  [CC2012-0805]
C130  Tolerance: 5%  [CC2012-0805]  (hidden comment: 56n)
C131  Tolerance: 5%  [CC2012-0805]  (hidden comment: 56n)
C132  220uF  [D]
C133  1u  [CC2012-0805]
C134  100u  [D]
C135  10u  [CC2012-0805]
C136  1uF  [CC2012-0805]
C137  1u  [CC1608-0603]
C138  100n  [CC1005-0402]
C139  100n  [CC1005-0402]
C140  1u  [CC2012-0805]
C141  100n  [CC1005-0402]
C142  1u  [CC1608-0603]
C143  10u  [CC2012-0805]
C144  100n  [CC1005-0402]
C145  220uF  [D]
C146  1u  [CC1608-0603]
C147  10u  [CC2012-0805]
C148  10uF  [CC3225-1210]
C149  220uF  [D]
C150  1uF  [CC2012-0805]
R40  Tolerance: 0.1%  [CR2012-0805]  (hidden comment: 2.26K)
R41  Tolerance: 0.1%  [CR2012-0805]  (hidden comment: 3.57K)
R42  NL  [CR2012-0805]
R43  10  [CR2012-0805]
R44  Tolerance: 0.1%  [CR2012-0805]  (hidden comment: 1.13K)
R45  Tolerance: 0.1%  [CR2012-0805]  (hidden comment: 1.30K)
R46  Tolerance: 0.1%  [CR2012-0805]  (hidden comment: 1.30K)
R47  Tolerance: 0.1%  [CR2012-0805]  (hidden comment: 2.00K)
R48  Tolerance: 0.1%  [CR2012-0805]  (hidden comment: 649)
R49  Tolerance: 0.1%  [CR2012-0805]  (hidden comment: 649)
R50  Tolerance: 0.1%  [CR2012-0805]  (hidden comment: 604)
R51  Tolerance: 0.1%  [CR2012-0805]  (hidden comment: 604)
R52  39.2  [CR2012-0805]
R53  39.2  [CR2012-0805]
R54  Tolerance: 0.1%  [CR2012-0805]  (hidden comment: 100K)
R55  Tolerance: 0.1%  [CR2012-0805]  (hidden comment: 100K)
R56  3.32K  [CR2012-0805]
R57  100K  [CR2012-0805]
U14  AD829JR  [R-8D]
U15  AD829JR  [R-8D]
U16  AD829JR  [R-8D]
U17  AD8672AR  [R-8]  (parts A,B of 2)
U18  AD7679  [LQFP7x7-G48/N]

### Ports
BUSY (out), CONV (in), D00 (out), D01 (out), D02 (out), D03 (out), D04 (out), D05 (out), D06 (out), D07 (out), D08 (out), D09 (out), D10 (out), D11 (out), D12 (out), D13 (out), D14 (out), D15 (out), D16 (out), D17 (out), DITHER (in), REF5 (in)

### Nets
+5V: C132.1 C135.2 C137.2 C138.2 C141.2 U18.2(AVDD) U18.47(AVDD)
+15V: C118.1 C125.1 C126.1 C136.1 U14.7(V+) U15.7(V+) U16.7(V+) U17.8(V+)
-15V: C117.1 C123.1 C124.1 U14.4(V-) U15.4(V-) U16.4(V-)
AGND: C116.2 C117.2 C118.2 C120.2 C121.2 C122.2 C123.2 C124.2 C125.2 C126.2 C128.2 C129.2 C130.2 C131.2 C132.2 C133.2 C134.2 C135.1 C136.2 C137.1 C138.1 C140.2 C141.1 C150.2 R43.2 R46.2 R54.2 U17.4(V-) U18.1(AGND) U18.36(AGND) U18.38(REFGND) U18.44(AGND) U18.46(REFBUFIN)
GND: C139.1 C142.1 C143.1 C144.1 C145.2 C146.1 C147.1 C149.2 U18.3(MODE0) U18.4(MODE1) U18.17(OGND) U18.20(DGND) U18.30(DGND) U18.31(~{RD}) U18.32(~{CS}) U18.33(RESET) U18.34(PD)
VCC: C139.2 C142.2 C143.2 C145.1 U18.19(DVDD) U18.48(PDBUF)
VDD: C144.2 C146.2 C147.2 C149.1 U18.18(OVDD)
ADCIN: R40.2 ; off-sheet ADCIN
BUSY: U18.29(BUSY) ; port BUSY
CONV: U18.35(~{CNVST}) ; port CONV
D00: U18.5(D0/OB/~{2C}) ; port D00
D01: U18.8(D1/A0) ; port D01
D02: U18.9(D2/A1) ; port D02
D03: U18.10(D3) ; port D03
D04: U18.11(D4/DIVSCLK0) ; port D04
D05: U18.12(D5/DIVSCKL1) ; port D05
D06: U18.13(D6/EXT/~{INT}) ; port D06
D07: U18.14(D7/INVSYNC) ; port D07
D08: U18.15(D8/INVSCKL) ; port D08
D09: U18.16(D9/RDC/SDIN) ; port D09
D10: U18.21(D10/SDOUT) ; port D10
D11: U18.22(D11/SCLK) ; port D11
D12: U18.23(D12/SYNC) ; port D12
D13: U18.24(D13/RDERROR) ; port D13
D14: U18.25(D14) ; port D14
D15: U18.26(D15) ; port D15
D16: U18.27(D16) ; port D16
D17: U18.28(D17) ; port D17
DITHER: R42.2 ; port DITHER
REF2.5: C122.1 R48.2 U16.3(IN+) U17.1(OUT) U17.2(IN-)
REF5: C150.1 R55.1 U17.5(IN+) ; port REF5
NetC116_1: C116.1 R40.1 R41.2 R44.2
NetC119_1: C119.1 R44.1 R45.2 U14.6(OUT)
NetC119_2: C119.2 R41.1 U14.2(IN-)
NetC120_1: C120.1 U14.5(C_COMP)
NetC121_1: C121.1 R45.1 R47.2 R49.2
NetC127_1: C127.1 R49.1 R50.1 R53.2 U15.6(OUT)
NetC127_2: C127.2 R47.1 U15.2(IN-)
NetC128_1: C128.1 U15.5(C_COMP)
NetC129_1: C129.1 U16.5(C_COMP)
NetC130_1: C130.1 R53.1 U18.43(IN+)
NetC131_1: C131.1 R52.1 U18.39(IN-)
NetC133_1: C133.1 C134.1 R56.2 R57.2 U18.37(REF)
NetC140_1: C140.1 R54.1 R55.2 U17.3(IN+)
NetC148_1: C148.1 R57.1 U17.6(IN-)
NetC148_2: C148.2 R56.1 U17.7(OUT)
NetR42_1: R42.1 R43.1 U14.3(IN+)
NetR46_1: R46.1 R48.1 U15.3(IN+)
NetR50_2: R50.2 R51.2 U16.2(IN-)
NetR51_1: R51.1 R52.2 U16.6(OUT)

Not connected (* = marked no-connect by the designer): U14 1(OS_NUL)* 8(OS_NUL)*; U15 1(OS_NUL)* 8(OS_NUL)*; U16 1(OS_NUL)* 8(OS_NUL)*

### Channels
FPGA1/ADC1: designators end in A; ports BUSY=BUSY1 CONV=CONV1 D00=D001 D01=D011 D02=D021 D03=D031 D04=D041 D05=D051 D06=D061 D07=D071 D08=D081 D09=D091 D10=D101 D11=D111 D12=D121 D13=D131 D14=D141 D15=D151 D16=D161 D17=D171 DITHER=DITHER_FPGA1 REF5=REF5_FPGA1
FPGA1/ADC2: designators end in B; ports BUSY=BUSY2 CONV=CONV2 D00=D002 D01=D012 D02=D022 D03=D032 D04=D042 D05=D052 D06=D062 D07=D072 D08=D082 D09=D092 D10=D102 D11=D112 D12=D122 D13=D132 D14=D142 D15=D152 D16=D162 D17=D172 DITHER=DITHER_FPGA1 REF5=REF5_FPGA1
FPGA1/ADC3: designators end in C; ports BUSY=BUSY3 CONV=CONV3 D00=D003 D01=D013 D02=D023 D03=D033 D04=D043 D05=D053 D06=D063 D07=D073 D08=D083 D09=D093 D10=D103 D11=D113 D12=D123 D13=D133 D14=D143 D15=D153 D16=D163 D17=D173 DITHER=DITHER_FPGA1 REF5=REF5_FPGA1
FPGA1/ADC4: designators end in D; ports BUSY=BUSY4 CONV=CONV4 D00=D004 D01=D014 D02=D024 D03=D034 D04=D044 D05=D054 D06=D064 D07=D074 D08=D084 D09=D094 D10=D104 D11=D114 D12=D124 D13=D134 D14=D144 D15=D154 D16=D164 D17=D174 DITHER=DITHER_FPGA1 REF5=REF5_FPGA1
FPGA1/ADC5: designators end in E; ports BUSY=BUSY5 CONV=CONV5 D00=D005 D01=D015 D02=D025 D03=D035 D04=D045 D05=D055 D06=D065 D07=D075 D08=D085 D09=D095 D10=D105 D11=D115 D12=D125 D13=D135 D14=D145 D15=D155 D16=D165 D17=D175 DITHER=DITHER_FPGA1 REF5=REF5_FPGA1
FPGA1/ADC6: designators end in F; ports BUSY=BUSY6 CONV=CONV6 D00=D006 D01=D016 D02=D026 D03=D036 D04=D046 D05=D056 D06=D066 D07=D076 D08=D086 D09=D096 D10=D106 D11=D116 D12=D126 D13=D136 D14=D146 D15=D156 D16=D166 D17=D176 DITHER=DITHER_FPGA1 REF5=REF5_FPGA1
FPGA1/ADC7: designators end in G; ports BUSY=BUSY7 CONV=CONV7 D00=D007 D01=D017 D02=D027 D03=D037 D04=D047 D05=D057 D06=D067 D07=D077 D08=D087 D09=D097 D10=D107 D11=D117 D12=D127 D13=D137 D14=D147 D15=D157 D16=D167 D17=D177 DITHER=DITHER_FPGA1 REF5=REF5_FPGA1
FPGA1/ADC8: designators end in H; ports BUSY=BUSY8 CONV=CONV8 D00=D008 D01=D018 D02=D028 D03=D038 D04=D048 D05=D058 D06=D068 D07=D078 D08=D088 D09=D098 D10=D108 D11=D118 D12=D128 D13=D138 D14=D148 D15=D158 D16=D168 D17=D178 DITHER=DITHER_FPGA1 REF5=REF5_FPGA1
FPGA2/ADC1: designators end in I; ports BUSY=BUSY1 CONV=CONV1 D00=D001 D01=D011 D02=D021 D03=D031 D04=D041 D05=D051 D06=D061 D07=D071 D08=D081 D09=D091 D10=D101 D11=D111 D12=D121 D13=D131 D14=D141 D15=D151 D16=D161 D17=D171 DITHER=DITHER_FPGA2 REF5=REF5_FPGA2
FPGA2/ADC2: designators end in J; ports BUSY=BUSY2 CONV=CONV2 D00=D002 D01=D012 D02=D022 D03=D032 D04=D042 D05=D052 D06=D062 D07=D072 D08=D082 D09=D092 D10=D102 D11=D112 D12=D122 D13=D132 D14=D142 D15=D152 D16=D162 D17=D172 DITHER=DITHER_FPGA2 REF5=REF5_FPGA2
FPGA2/ADC3: designators end in K; ports BUSY=BUSY3 CONV=CONV3 D00=D003 D01=D013 D02=D023 D03=D033 D04=D043 D05=D053 D06=D063 D07=D073 D08=D083 D09=D093 D10=D103 D11=D113 D12=D123 D13=D133 D14=D143 D15=D153 D16=D163 D17=D173 DITHER=DITHER_FPGA2 REF5=REF5_FPGA2
FPGA2/ADC4: designators end in L; ports BUSY=BUSY4 CONV=CONV4 D00=D004 D01=D014 D02=D024 D03=D034 D04=D044 D05=D054 D06=D064 D07=D074 D08=D084 D09=D094 D10=D104 D11=D114 D12=D124 D13=D134 D14=D144 D15=D154 D16=D164 D17=D174 DITHER=DITHER_FPGA2 REF5=REF5_FPGA2
FPGA2/ADC5: designators end in M; ports BUSY=BUSY5 CONV=CONV5 D00=D005 D01=D015 D02=D025 D03=D035 D04=D045 D05=D055 D06=D065 D07=D075 D08=D085 D09=D095 D10=D105 D11=D115 D12=D125 D13=D135 D14=D145 D15=D155 D16=D165 D17=D175 DITHER=DITHER_FPGA2 REF5=REF5_FPGA2
FPGA2/ADC6: designators end in N; ports BUSY=BUSY6 CONV=CONV6 D00=D006 D01=D016 D02=D026 D03=D036 D04=D046 D05=D056 D06=D066 D07=D076 D08=D086 D09=D096 D10=D106 D11=D116 D12=D126 D13=D136 D14=D146 D15=D156 D16=D166 D17=D176 DITHER=DITHER_FPGA2 REF5=REF5_FPGA2
FPGA2/ADC7: designators end in O; ports BUSY=BUSY7 CONV=CONV7 D00=D007 D01=D017 D02=D027 D03=D037 D04=D047 D05=D057 D06=D067 D07=D077 D08=D087 D09=D097 D10=D107 D11=D117 D12=D127 D13=D137 D14=D147 D15=D157 D16=D167 D17=D177 DITHER=DITHER_FPGA2 REF5=REF5_FPGA2
FPGA2/ADC8: designators end in P; ports BUSY=BUSY8 CONV=CONV8 D00=D008 D01=D018 D02=D028 D03=D038 D04=D048 D05=D058 D06=D068 D07=D078 D08=D088 D09=D098 D10=D108 D11=D118 D12=D128 D13=D138 D14=D148 D15=D158 D16=D168 D17=D178 DITHER=DITHER_FPGA2 REF5=REF5_FPGA2

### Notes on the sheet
- 5th order Cheby, 200kHz cut-off, 0.5dB ripple
- 16 Channel ADC: ADC
- D050361
- 7
- 11
- A
- Daniel Sigg

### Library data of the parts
C116-C131 C133 C135-C144 C146-C148 C150 = Cap Semi: Capacitor (Semiconductor SIM Model)
C132 C145 C149 = T494D: Solid Tantalum Chip Capacitor, Standard T494 Series - Low ESR, Industrial Grade; Part Number: PCE3603CT-ND
C134 = T494D: Solid Tantalum Chip Capacitor, Standard T494 Series - Low ESR, Industrial Grade
R40-R56 = Res2: Resistor
R57 = Res2: Resistor; Tolerance: 0.1%
U14-U16 = AD829JR: as U9 on sheet StdADC06
U17 = OP292GS: Dual Single-Supply Operational Amplifier; PackageDocument: REV. B
U18 = AD7679AST: 18 bit SAR ADC, 570kSPS

## Sheet StdADC09.SchDoc
size B; PageSetup: Record=PageOptions|CenterHorizontal=True|CenterVertical=True|PrintScale=1.08|XCorrection=1.00|YCorrection=1.00|PrintKind=1|BorderSize=5000000|LeftOffset=0|BottomOffset=0|Orientation=2|PaperLength=1000|PaperWidth=1000|Scale=100|PaperSource=15|PrintQuality=600|MediaType=1|DitherType=10|PaperKind=11x17|PrintScaleMode=1
Used 2 times, as channels FPGA1/DAC, FPGA2/DAC. Parts and nets are listed once, with the designators drawn on the sheet.
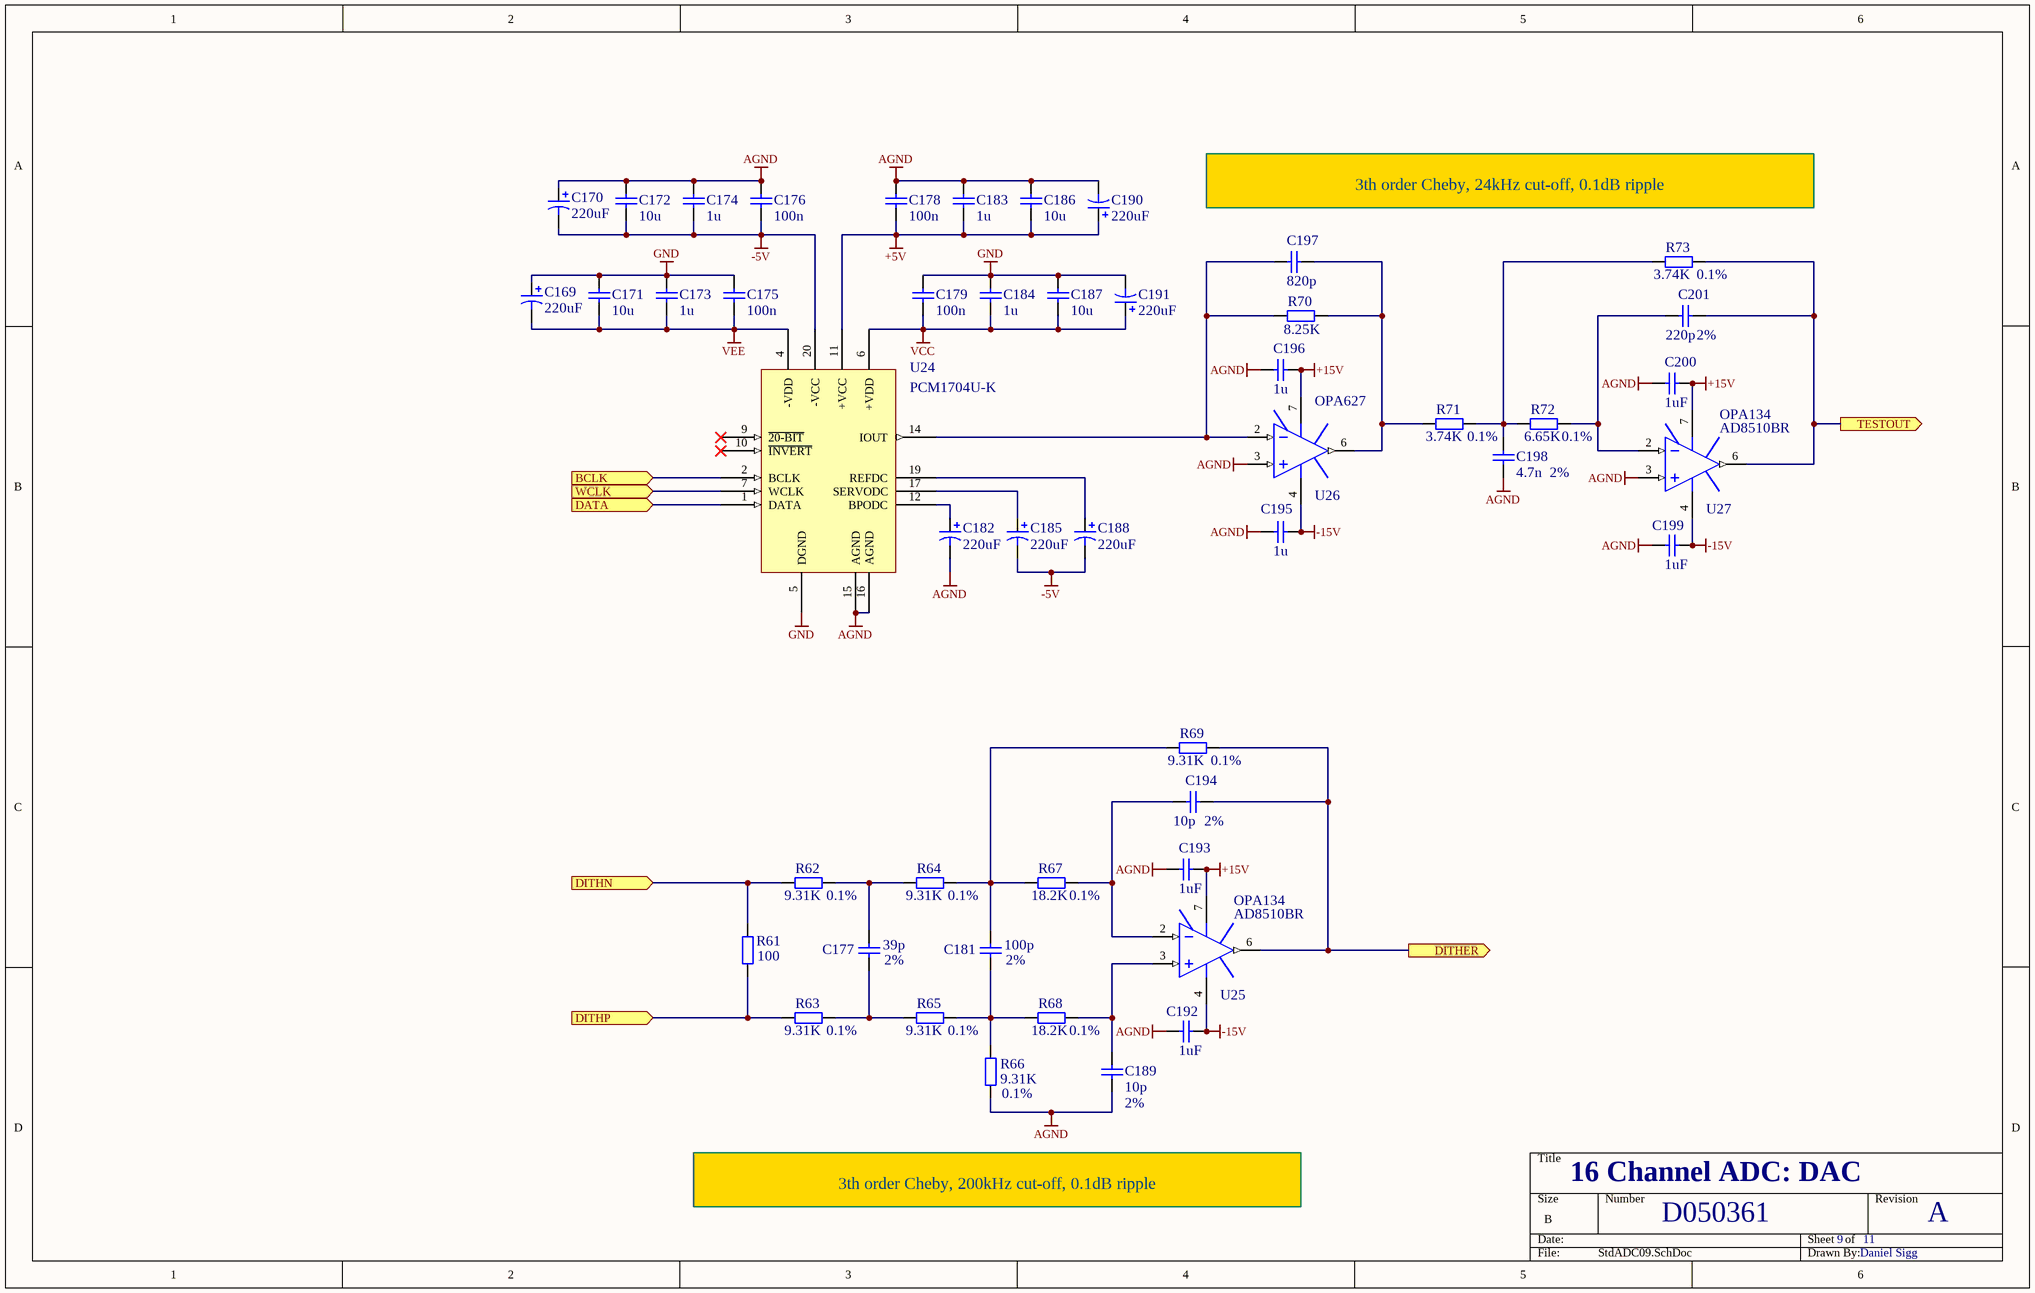
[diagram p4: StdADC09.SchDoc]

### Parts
C169  220uF  [D]
C170  220uF  [D]
C171  10u  [CC2012-0805]
C172  10u  [CC2012-0805]
C173  1u  [CC1608-0603]
C174  1u  [CC1608-0603]
C175  100n  [CC1005-0402]
C176  100n  [CC1005-0402]
C177  Tolerance: 2%  [CC2012-0805]  (hidden comment: 39p)
C178  100n  [CC1005-0402]
C179  100n  [CC1005-0402]
C181  Tolerance: 2%  [CC2012-0805]  (hidden comment: 100p)
C182  220uF  [D]
C183  1u  [CC1608-0603]
C184  1u  [CC1608-0603]
C185  220uF  [D]
C186  10u  [CC2012-0805]
C187  10u  [CC2012-0805]
C188  220uF  [D]
C189  Tolerance: 2%  [CC2012-0805]  (hidden comment: 10p)
C190  220uF  [D]
C191  220uF  [D]
C192  1uF  [CC2012-0805]
C193  1uF  [CC2012-0805]
C194  Tolerance: 2%  [CC2012-0805]  (hidden comment: 10p)
C195  1u  [CC2012-0805]
C196  1u  [CC2012-0805]
C197  820p  [CC2012-0805]
C198  Tolerance: 2%  [CC2012-0805]  (hidden comment: 4.7n)
C199  1uF  [CC2012-0805]
C200  1uF  [CC2012-0805]
C201  Tolerance: 2%  [CC2012-0805]  (hidden comment: 220p)
R61  100  [CR2012-0805]
R62  Tolerance: 0.1%  [CR2012-0805]  (hidden comment: 9.31K)
R63  Tolerance: 0.1%  [CR2012-0805]  (hidden comment: 9.31K)
R64  Tolerance: 0.1%  [CR2012-0805]  (hidden comment: 9.31K)
R65  Tolerance: 0.1%  [CR2012-0805]  (hidden comment: 9.31K)
R66  Tolerance: 0.1%  [CR2012-0805]  (hidden comment: 9.31K)
R67  Tolerance: 0.1%  [CR2012-0805]  (hidden comment: 18.2K)
R68  Tolerance: 0.1%  [CR2012-0805]  (hidden comment: 18.2K)
R69  Tolerance: 0.1%  [CR2012-0805]  (hidden comment: 9.31K)
R70  8.25K  [CR2012-0805]
R71  Tolerance: 0.1%  [CR2012-0805]  (hidden comment: 3.74K)
R72  Tolerance: 0.1%  [CR2012-0805]  (hidden comment: 6.65K)
R73  Tolerance: 0.1%  [CR2012-0805]  (hidden comment: 3.74K)
U24  PCM1704U-K  [SO-G20/C6.9]
U25  OPA134  Alternative: AD8510BR  [R-8D]
U26  OPA627  [R-8D]
U27  OPA134  Alternative: AD8510BR  [R-8D]

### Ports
BCLK (in), DATA (in), DITHER (out), DITHN (in), DITHP (in), TESTOUT (out), WCLK (in)

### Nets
+5V: C178.2 C183.2 C186.2 C190.1 U24.11(+VCC)
+15V: C193.1 C196.1 C200.1 U25.7(V+) U26.7(V+) U27.7(V+)
-5V: C170.2 C172.2 C174.2 C176.2 C185.2 C188.2 U24.20(-VCC)
-15V: C192.1 C195.1 C199.1 U25.4(V-) U26.4(V-) U27.4(V-)
AGND: C170.1 C172.1 C174.1 C176.1 C178.1 C182.2 C183.1 C186.1 C189.2 C190.2 C192.2 C193.2 C195.2 C196.2 C198.2 C199.2 C200.2 R66.2 U24.15(AGND) U24.16(AGND) U26.3(IN+) U27.3(IN+)
GND: C169.1 C171.1 C173.1 C175.1 C179.1 C184.1 C187.1 C191.2 U24.5(DGND)
VCC: C179.2 C184.2 C187.2 C191.1 U24.6(+VDD)
VEE: C169.2 C171.2 C173.2 C175.2 U24.4(-VDD)
BCLK: U24.2(BCLK) ; port BCLK
DATA: U24.1(DATA) ; port DATA
DITHER: C194.1 R69.1 U25.6(OUT) ; port DITHER
DITHN: R61.1 R62.2 ; port DITHN
DITHP: R61.2 R63.2 ; port DITHP
TESTOUT: C201.1 R73.1 U27.6(OUT) ; port TESTOUT
WCLK: U24.7(WCLK) ; port WCLK
NetC177_1: C177.1 R62.1 R64.2
NetC177_2: C177.2 R63.1 R65.2
NetC181_1: C181.1 R64.1 R67.2 R69.2
NetC181_2: C181.2 R65.1 R66.1 R68.2
NetC182_1: C182.1 U24.12(BPODC)
NetC185_1: C185.1 U24.17(SERVODC)
NetC188_1: C188.1 U24.19(REFDC)
NetC189_1: C189.1 R68.1 U25.3(IN+)
NetC194_2: C194.2 R67.1 U25.2(IN-)
NetC197_1: C197.1 R70.1 R71.2 U26.6(OUT)
NetC197_2: C197.2 R70.2 U24.14(IOUT) U26.2(IN-)
NetC198_1: C198.1 R71.1 R72.2 R73.2
NetC201_2: C201.2 R72.1 U27.2(IN-)

Not connected (* = marked no-connect by the designer): U24 3(NC) 8(NC) 9(~{20-BIT})* 10(~{INVERT})* 13(NC) 18(NC); U25 1(OS_NUL) 5(C_COMP) 8(OS_NUL); U26 1(OS_NUL) 5(C_COMP) 8(OS_NUL); U27 1(OS_NUL) 5(C_COMP) 8(OS_NUL)

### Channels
FPGA1/DAC: designators end in A; ports BCLK=DBCLK DATA=DDATA DITHER=DITHER_FPGA1 DITHN=DITHN DITHP=DITHP TESTOUT=TEST_FPGA1 WCLK=DWCLK
FPGA2/DAC: designators end in B; ports BCLK=DBCLK DATA=DDATA DITHER=DITHER_FPGA2 DITHN=DITHN DITHP=DITHP TESTOUT=TEST_FPGA2 WCLK=DWCLK

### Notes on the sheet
- 3th order Cheby, 24kHz cut-off, 0.1dB ripple
- 3th order Cheby, 200kHz cut-off, 0.1dB ripple
- 16 Channel ADC: DAC
- D050361
- 9
- 11
- A
- Daniel Sigg

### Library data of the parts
C169 C170 C182 C185 C188 C190 C191 = T494D: as C132 on sheet StdADC07
C171-C179 C181 C183 C184 C186 C187 C189 C192-C201 = Cap Semi: Capacitor (Semiconductor SIM Model)
R61-R69 R71-R73 = Res2: Resistor
R70 = Res2: Resistor; Tolerance: 1%
U24 = PCM1704: 24 bit Sign-Magnitude DAC, 96kSPS
U25-U27 = AD829JR: as U9 on sheet StdADC06

## Sheet StdADC03.SchDoc
size B
Used 2 times, as channels FPGA1, FPGA2. Parts and nets are listed once, with the designators drawn on the sheet.
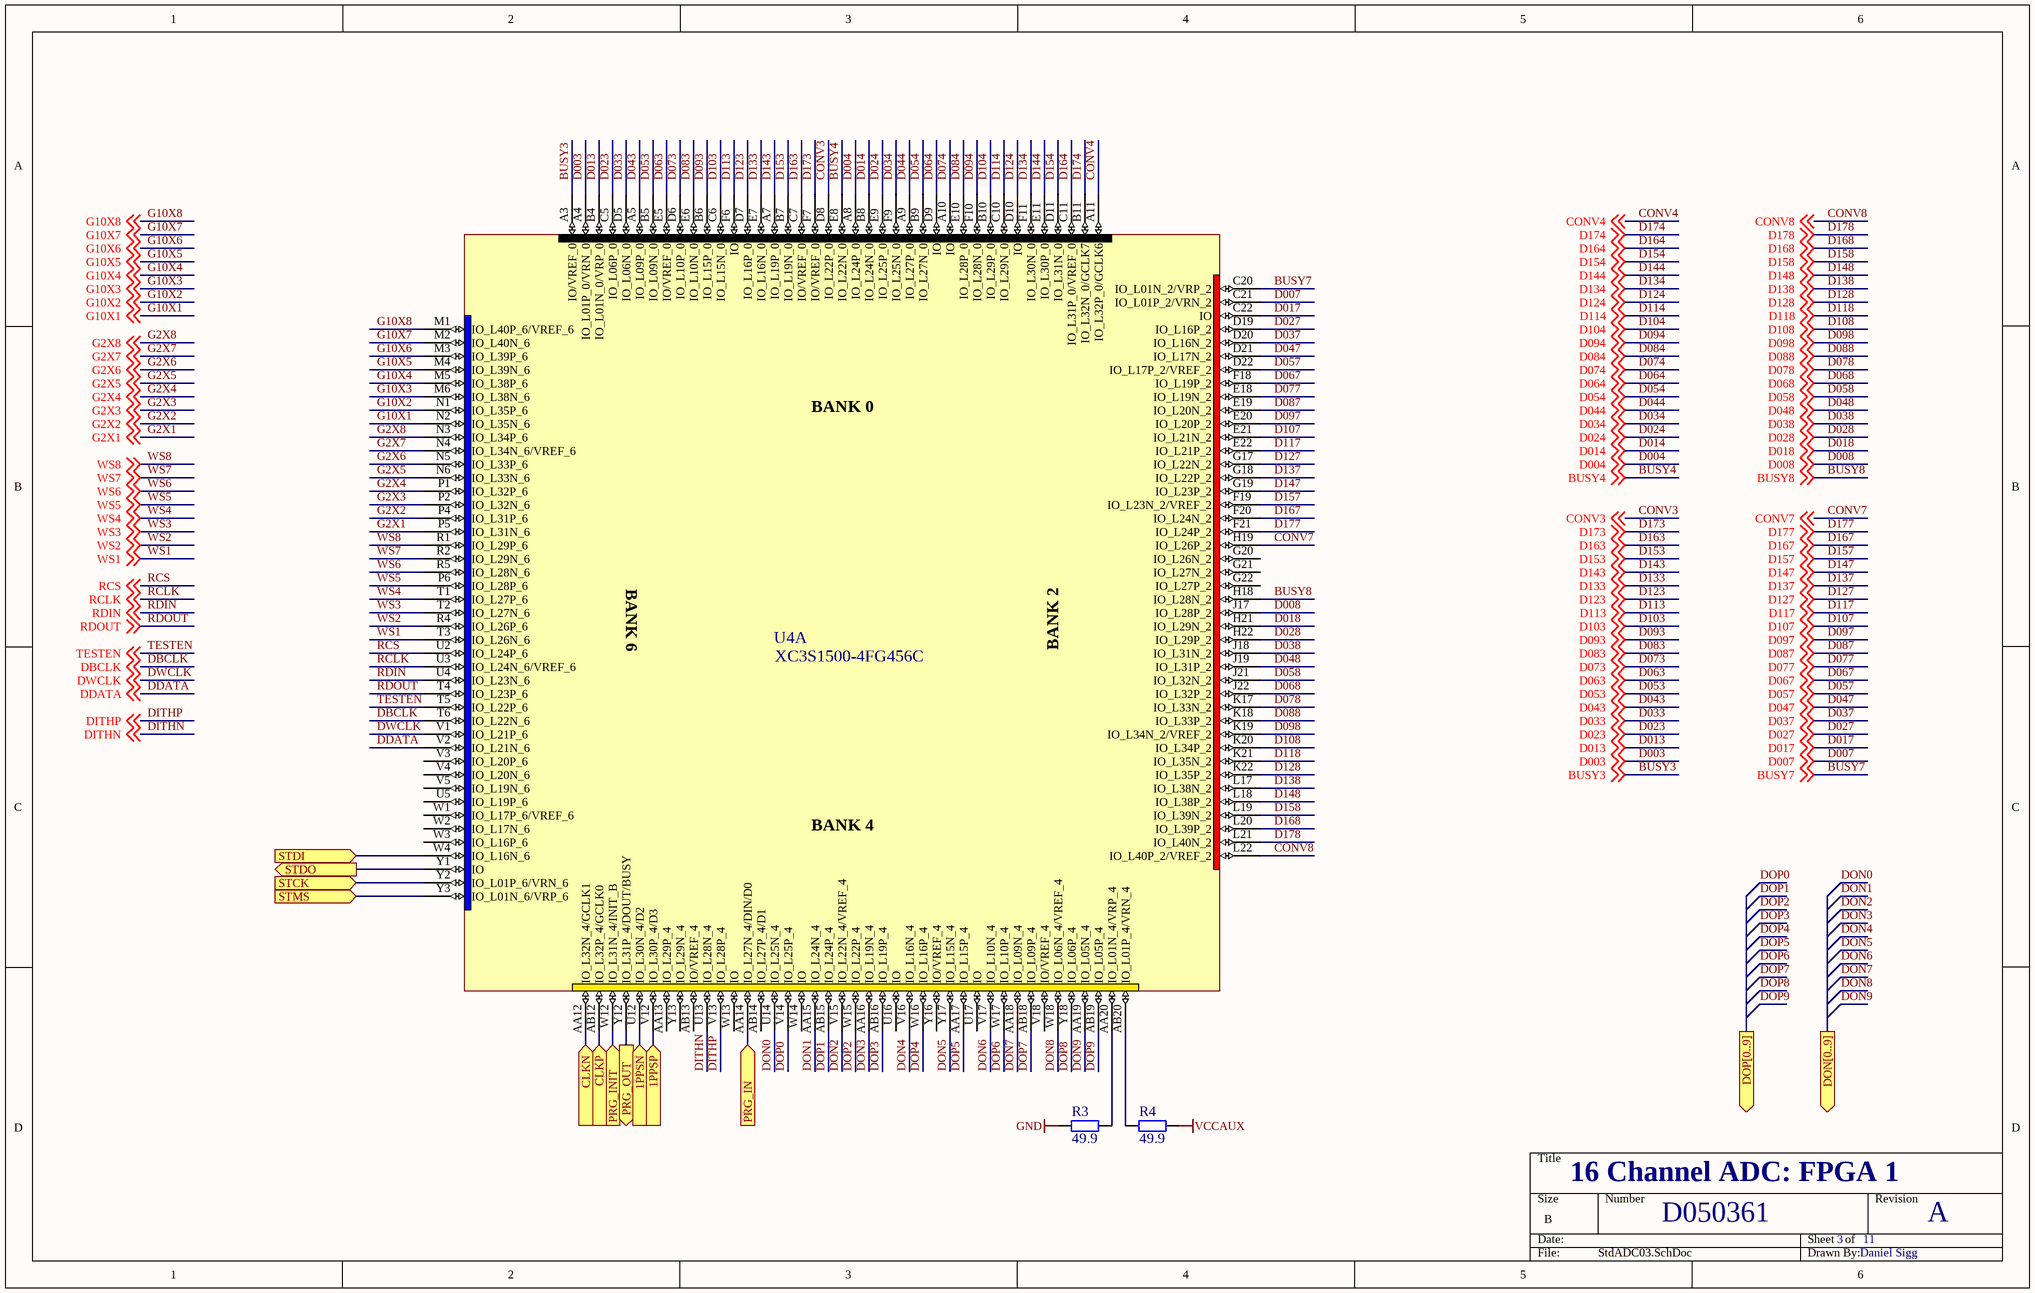
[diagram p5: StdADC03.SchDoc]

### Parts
R3  49.9  [CR2012-0805]
R4  49.9  [CR2012-0805]
U4  XC3S1500-4FG456C  [FG456]  (part A of 3)

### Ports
1PPSN (in), 1PPSP (in), CLKN (in), CLKP (in), DON[0..9] (out), DOP[0..9] (out), PRG_IN (in), PRG_INIT (in), PRG_OUT (out), STCK (in), STDI (in), STDO (out), STMS (in)

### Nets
GND: R3.1
VCCAUX: R4.2
1PPSN: U4.U12(IO_L30N_4/D2) ; port 1PPSN
1PPSP: U4.V12(IO_L30P_4/D3) ; port 1PPSP
BUSY3: U4.A3(IO/VREF_0) ; off-sheet BUSY3
BUSY4: U4.E8(IO_L22N_0) ; off-sheet BUSY4
BUSY7: U4.C20(IO_L01N_2/VRP_2) ; off-sheet BUSY7
BUSY8: U4.H18(IO_L28N_2) ; off-sheet BUSY8
CLKN: U4.AA12(IO_L32N_4/GCLK1) ; port CLKN
CLKP: U4.AB12(IO_L32P_4/GCLK0) ; port CLKP
CONV3: U4.D8(IO_L22P_0) ; off-sheet CONV3
CONV4: U4.A11(IO_L32P_0/GCLK6) ; off-sheet CONV4
CONV7: U4.H19(IO_L26P_2) ; off-sheet CONV7
CONV8: U4.L22(IO_L40P_2/VREF_2) ; off-sheet CONV8
D003: U4.A4(IO_L01P_0/VRN_0) ; off-sheet D003
D004: U4.A8(IO_L24P_0) ; off-sheet D004
D007: U4.C21(IO_L01P_2/VRN_2) ; off-sheet D007
D008: U4.J17(IO_L28P_2) ; off-sheet D008
D013: U4.B4(IO_L01N_0/VRP_0) ; off-sheet D013
D014: U4.B8(IO_L24N_0) ; off-sheet D014
D017: U4.C22(IO) ; off-sheet D017
D018: U4.H21(IO_L29N_2) ; off-sheet D018
D023: U4.C5(IO_L06P_0) ; off-sheet D023
D024: U4.E9(IO_L25P_0) ; off-sheet D024
D027: U4.D19(IO_L16P_2) ; off-sheet D027
D028: U4.H22(IO_L29P_2) ; off-sheet D028
D033: U4.D5(IO_L06N_0) ; off-sheet D033
D034: U4.F9(IO_L25N_0) ; off-sheet D034
D037: U4.D20(IO_L16N_2) ; off-sheet D037
D038: U4.J18(IO_L31N_2) ; off-sheet D038
D043: U4.A5(IO_L09P_0) ; off-sheet D043
D044: U4.A9(IO_L27P_0) ; off-sheet D044
D047: U4.D21(IO_L17N_2) ; off-sheet D047
D048: U4.J19(IO_L31P_2) ; off-sheet D048
D053: U4.B5(IO_L09N_0) ; off-sheet D053
D054: U4.B9(IO_L27N_0) ; off-sheet D054
D057: U4.D22(IO_L17P_2/VREF_2) ; off-sheet D057
D058: U4.J21(IO_L32N_2) ; off-sheet D058
D063: U4.E5(IO/VREF_0) ; off-sheet D063
D064: U4.D9(IO) ; off-sheet D064
D067: U4.F18(IO_L19P_2) ; off-sheet D067
D068: U4.J22(IO_L32P_2) ; off-sheet D068
D073: U4.D6(IO_L10P_0) ; off-sheet D073
D074: U4.A10(IO) ; off-sheet D074
D077: U4.E18(IO_L19N_2) ; off-sheet D077
D078: U4.K17(IO_L33N_2) ; off-sheet D078
D083: U4.E6(IO_L10N_0) ; off-sheet D083
D084: U4.E10(IO_L28P_0) ; off-sheet D084
D087: U4.E19(IO_L20N_2) ; off-sheet D087
D088: U4.K18(IO_L33P_2) ; off-sheet D088
D093: U4.B6(IO_L15P_0) ; off-sheet D093
D094: U4.F10(IO_L28N_0) ; off-sheet D094
D097: U4.E20(IO_L20P_2) ; off-sheet D097
D098: U4.K19(IO_L34N_2/VREF_2) ; off-sheet D098
D103: U4.C6(IO_L15N_0) ; off-sheet D103
D104: U4.B10(IO_L29P_0) ; off-sheet D104
D107: U4.E21(IO_L21N_2) ; off-sheet D107
D108: U4.K20(IO_L34P_2) ; off-sheet D108
D113: U4.F6(IO) ; off-sheet D113
D114: U4.C10(IO_L29N_0) ; off-sheet D114
D117: U4.E22(IO_L21P_2) ; off-sheet D117
D118: U4.K21(IO_L35N_2) ; off-sheet D118
D123: U4.D7(IO_L16P_0) ; off-sheet D123
D124: U4.D10(IO) ; off-sheet D124
D127: U4.G17(IO_L22N_2) ; off-sheet D127
D128: U4.K22(IO_L35P_2) ; off-sheet D128
D133: U4.E7(IO_L16N_0) ; off-sheet D133
D134: U4.F11(IO_L30N_0) ; off-sheet D134
D137: U4.G18(IO_L22P_2) ; off-sheet D137
D138: U4.L17(IO_L38N_2) ; off-sheet D138
D143: U4.A7(IO_L19P_0) ; off-sheet D143
D144: U4.E11(IO_L30P_0) ; off-sheet D144
D147: U4.G19(IO_L23P_2) ; off-sheet D147
D148: U4.L18(IO_L38P_2) ; off-sheet D148
D153: U4.B7(IO_L19N_0) ; off-sheet D153
D154: U4.D11(IO_L31N_0) ; off-sheet D154
D157: U4.F19(IO_L23N_2/VREF_2) ; off-sheet D157
D158: U4.L19(IO_L39N_2) ; off-sheet D158
D163: U4.C7(IO/VREF_0) ; off-sheet D163
D164: U4.C11(IO_L31P_0/VREF_0) ; off-sheet D164
D167: U4.F20(IO_L24N_2) ; off-sheet D167
D168: U4.L20(IO_L39P_2) ; off-sheet D168
D173: U4.F7(IO/VREF_0) ; off-sheet D173
D174: U4.B11(IO_L32N_0/GCLK7) ; off-sheet D174
D177: U4.F21(IO_L24P_2) ; off-sheet D177
D178: U4.L21(IO_L40N_2) ; off-sheet D178
DBCLK: U4.T6(IO_L22N_6) ; off-sheet DBCLK
DDATA: U4.V2(IO_L21N_6) ; off-sheet DDATA
DITHN: U4.U13(IO_L28N_4) ; off-sheet DITHN
DITHP: U4.V13(IO_L28P_4) ; off-sheet DITHP
DON0: U4.U14(IO_L25N_4)
DON1: U4.AA15(IO_L24N_4)
DON2: U4.V15(IO_L22N_4/VREF_4)
DON3: U4.AA16(IO_L19N_4)
DON4: U4.V16(IO_L16N_4)
DON5: U4.Y17(IO_L15N_4)
DON6: U4.V17(IO_L10N_4)
DON7: U4.AA18(IO_L09N_4)
DON8: U4.W18(IO_L06N_4/VREF_4)
DON9: U4.AA19(IO_L05N_4)
DOP0: U4.V14(IO_L25P_4)
DOP1: U4.AB15(IO_L24P_4)
DOP2: U4.W15(IO_L22P_4)
DOP3: U4.AB16(IO_L19P_4)
DOP4: U4.W16(IO_L16P_4)
DOP5: U4.AA17(IO_L15P_4)
DOP6: U4.W17(IO_L10P_4)
DOP7: U4.AB18(IO_L09P_4)
DOP8: U4.Y18(IO_L06P_4)
DOP9: U4.AB19(IO_L05P_4)
DWCLK: U4.V1(IO_L21P_6) ; off-sheet DWCLK
G2X1: U4.P5(IO_L31N_6) ; off-sheet G2X1
G2X2: U4.P4(IO_L31P_6) ; off-sheet G2X2
G2X3: U4.P2(IO_L32N_6) ; off-sheet G2X3
G2X4: U4.P1(IO_L32P_6) ; off-sheet G2X4
G2X5: U4.N6(IO_L33N_6) ; off-sheet G2X5
G2X6: U4.N5(IO_L33P_6) ; off-sheet G2X6
G2X7: U4.N4(IO_L34N_6/VREF_6) ; off-sheet G2X7
G2X8: U4.N3(IO_L34P_6) ; off-sheet G2X8
G10X1: U4.N2(IO_L35N_6) ; off-sheet G10X1
G10X2: U4.N1(IO_L35P_6) ; off-sheet G10X2
G10X3: U4.M6(IO_L38N_6) ; off-sheet G10X3
G10X4: U4.M5(IO_L38P_6) ; off-sheet G10X4
G10X5: U4.M4(IO_L39N_6) ; off-sheet G10X5
G10X6: U4.M3(IO_L39P_6) ; off-sheet G10X6
G10X7: U4.M2(IO_L40N_6) ; off-sheet G10X7
G10X8: U4.M1(IO_L40P_6/VREF_6) ; off-sheet G10X8
PRG_IN: U4.AA14(IO_L27N_4/DIN/D0) ; port PRG_IN
PRG_INIT: U4.W12(IO_L31N_4/INIT_B) ; port PRG_INIT
PRG_OUT: U4.Y12(IO_L31P_4/DOUT/BUSY) ; port PRG_OUT
RCLK: U4.U3(IO_L24N_6/VREF_6) ; off-sheet RCLK
RCS: U4.U2(IO_L24P_6) ; off-sheet RCS
RDIN: U4.U4(IO_L23N_6) ; off-sheet RDIN
RDOUT: U4.T4(IO_L23P_6) ; off-sheet RDOUT
STCK: U4.Y2(IO_L01P_6/VRN_6) ; port STCK
STDI: U4.W4(IO_L16N_6) ; port STDI
STDO: U4.Y1(IO) ; port STDO
STMS: U4.Y3(IO_L01N_6/VRP_6) ; port STMS
TESTEN: U4.T5(IO_L22P_6) ; off-sheet TESTEN
WS1: U4.T3(IO_L26N_6) ; off-sheet WS1
WS2: U4.R4(IO_L26P_6) ; off-sheet WS2
WS3: U4.T2(IO_L27N_6) ; off-sheet WS3
WS4: U4.T1(IO_L27P_6) ; off-sheet WS4
WS5: U4.P6(IO_L28P_6) ; off-sheet WS5
WS6: U4.R5(IO_L28N_6) ; off-sheet WS6
WS7: U4.R2(IO_L29N_6) ; off-sheet WS7
WS8: U4.R1(IO_L29P_6) ; off-sheet WS8
NetR3_2: R3.2 U4.AA20(IO_L01N_4/VRP_4)
NetR4_1: R4.1 U4.AB20(IO_L01P_4/VRN_4)

Not connected (* = marked no-connect by the designer): U4 AA13(IO_L29P_4) AB13(IO/VREF_4) AB14(IO_L27P_4/D1) G20(IO_L26N_2) G21(IO_L27N_2) G22(IO_L27P_2) U5(IO_L19P_6) U16(IO) U17(IO) V3(IO_L20P_6) V4(IO_L20N_6) V5(IO_L19N_6) V18(IO/VREF_4) W1(IO_L17P_6/VREF_6) W2(IO_L17N_6) W3(IO_L16P_6) W13(IO) W14(IO) Y13(IO_L29N_4) Y16(IO/VREF_4)

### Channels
FPGA1: designators R3=R3A R4=R4A U4=U4A#1; ports 1PPSN=NetU2_9 1PPSP=NetU2_10 CLKN=NetU1_9 CLKP=NetU1_10 PRG_IN=NetU4A#1_AA14 PRG_INIT=NetU4A#1_W12 PRG_OUT=NetU4A#1_Y12 STCK=STCK STDI=STDI STDO=NetU4A#1_Y1 STMS=STMS
FPGA2: designators R3=R3B R4=R4B U4=U4B#1; ports 1PPSN=NetU2_6 1PPSP=NetU2_7 CLKN=NetU1_6 CLKP=NetU1_7 PRG_IN=NetU4A#1_Y12 PRG_INIT=NetU4A#1_W12 PRG_OUT=NetU4B#1_Y12 STCK=STCK STDI=NetU4A#1_Y1 STDO=STDO STMS=STMS

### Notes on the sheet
- 16 Channel ADC: FPGA 1
- D050361
- 3
- 11
- A
- Daniel Sigg

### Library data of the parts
R3 R4 = Res2: Resistor
U4 = XC3S1500-4FG456C: Spartan-3 1.2V FPGA, 333 User I/Os, 456-ball FBGA, Standard Performance, Commercial Grade; PackageDocument: ver1.1, Apr-2001

## Sheet StdADC04.SchDoc
size B
Used 2 times, as channels FPGA1, FPGA2. Parts and nets are listed once, with the designators drawn on the sheet.
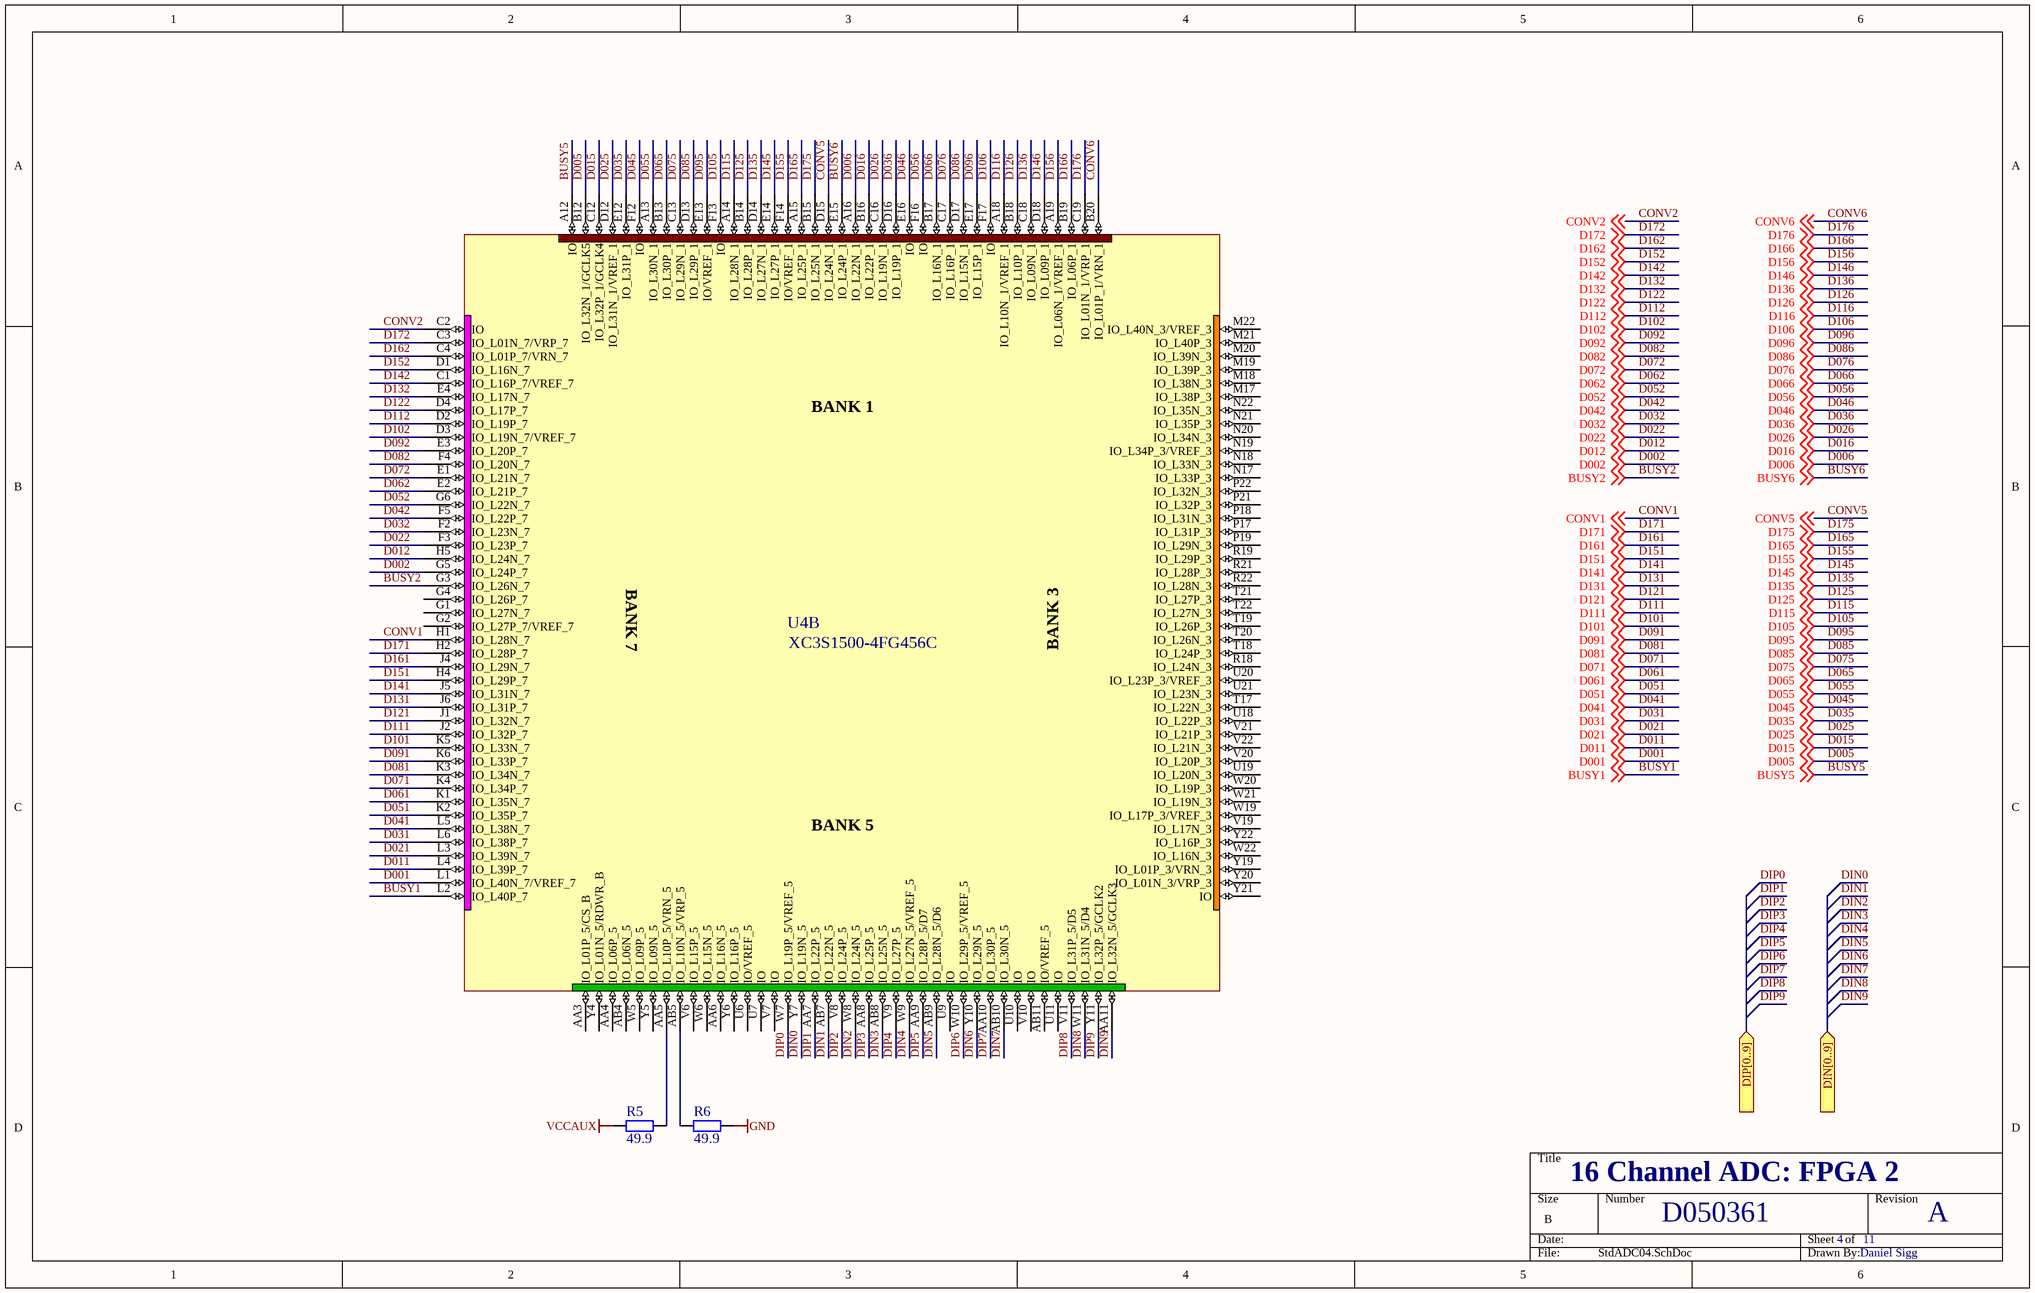
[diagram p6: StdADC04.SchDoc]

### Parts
R5  49.9  [CR2012-0805]
R6  49.9  [CR2012-0805]
U4  XC3S1500-4FG456C  [FG456]  (part B of 3)

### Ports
DIN[0..9] (in), DIP[0..9] (in)

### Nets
GND: R6.2
VCCAUX: R5.1
BUSY1: U4.L2(IO_L40P_7) ; off-sheet BUSY1
BUSY2: U4.G3(IO_L26N_7) ; off-sheet BUSY2
BUSY5: U4.A12(IO) ; off-sheet BUSY5
BUSY6: U4.E15(IO_L24P_1) ; off-sheet BUSY6
CONV1: U4.H1(IO_L28N_7) ; off-sheet CONV1
CONV2: U4.C2(IO) ; off-sheet CONV2
CONV5: U4.D15(IO_L24N_1) ; off-sheet CONV5
CONV6: U4.B20(IO_L01P_1/VRN_1) ; off-sheet CONV6
D001: U4.L1(IO_L40N_7/VREF_7) ; off-sheet D001
D002: U4.G5(IO_L24P_7) ; off-sheet D002
D005: U4.B12(IO_L32N_1/GCLK5) ; off-sheet D005
D006: U4.A16(IO_L22N_1) ; off-sheet D006
D011: U4.L4(IO_L39P_7) ; off-sheet D011
D012: U4.H5(IO_L24N_7) ; off-sheet D012
D015: U4.C12(IO_L32P_1/GCLK4) ; off-sheet D015
D016: U4.B16(IO_L22P_1) ; off-sheet D016
D021: U4.L3(IO_L39N_7) ; off-sheet D021
D022: U4.F3(IO_L23P_7) ; off-sheet D022
D025: U4.D12(IO_L31N_1/VREF_1) ; off-sheet D025
D026: U4.C16(IO_L19N_1) ; off-sheet D026
D031: U4.L6(IO_L38P_7) ; off-sheet D031
D032: U4.F2(IO_L23N_7) ; off-sheet D032
D035: U4.E12(IO_L31P_1) ; off-sheet D035
D036: U4.D16(IO_L19P_1) ; off-sheet D036
D041: U4.L5(IO_L38N_7) ; off-sheet D041
D042: U4.F5(IO_L22P_7) ; off-sheet D042
D045: U4.F12(IO) ; off-sheet D045
D046: U4.E16(IO) ; off-sheet D046
D051: U4.K2(IO_L35P_7) ; off-sheet D051
D052: U4.G6(IO_L22N_7) ; off-sheet D052
D055: U4.A13(IO_L30N_1) ; off-sheet D055
D056: U4.F16(IO) ; off-sheet D056
D061: U4.K1(IO_L35N_7) ; off-sheet D061
D062: U4.E2(IO_L21P_7) ; off-sheet D062
D065: U4.B13(IO_L30P_1) ; off-sheet D065
D066: U4.B17(IO_L16N_1) ; off-sheet D066
D071: U4.K4(IO_L34P_7) ; off-sheet D071
D072: U4.E1(IO_L21N_7) ; off-sheet D072
D075: U4.C13(IO_L29N_1) ; off-sheet D075
D076: U4.C17(IO_L16P_1) ; off-sheet D076
D081: U4.K3(IO_L34N_7) ; off-sheet D081
D082: U4.F4(IO_L20N_7) ; off-sheet D082
D085: U4.D13(IO_L29P_1) ; off-sheet D085
D086: U4.D17(IO_L15N_1) ; off-sheet D086
D091: U4.K6(IO_L33P_7) ; off-sheet D091
D092: U4.E3(IO_L20P_7) ; off-sheet D092
D095: U4.E13(IO/VREF_1) ; off-sheet D095
D096: U4.E17(IO_L15P_1) ; off-sheet D096
D101: U4.K5(IO_L33N_7) ; off-sheet D101
D102: U4.D3(IO_L19N_7/VREF_7) ; off-sheet D102
D105: U4.F13(IO) ; off-sheet D105
D106: U4.F17(IO) ; off-sheet D106
D111: U4.J2(IO_L32P_7) ; off-sheet D111
D112: U4.D2(IO_L19P_7) ; off-sheet D112
D115: U4.A14(IO_L28N_1) ; off-sheet D115
D116: U4.A18(IO_L10N_1/VREF_1) ; off-sheet D116
D121: U4.J1(IO_L32N_7) ; off-sheet D121
D122: U4.D4(IO_L17P_7) ; off-sheet D122
D125: U4.B14(IO_L28P_1) ; off-sheet D125
D126: U4.B18(IO_L10P_1) ; off-sheet D126
D131: U4.J6(IO_L31P_7) ; off-sheet D131
D132: U4.E4(IO_L17N_7) ; off-sheet D132
D135: U4.D14(IO_L27N_1) ; off-sheet D135
D136: U4.C18(IO_L09N_1) ; off-sheet D136
D141: U4.J5(IO_L31N_7) ; off-sheet D141
D142: U4.C1(IO_L16P_7/VREF_7) ; off-sheet D142
D145: U4.E14(IO_L27P_1) ; off-sheet D145
D146: U4.D18(IO_L09P_1) ; off-sheet D146
D151: U4.H4(IO_L29P_7) ; off-sheet D151
D152: U4.D1(IO_L16N_7) ; off-sheet D152
D155: U4.F14(IO/VREF_1) ; off-sheet D155
D156: U4.A19(IO_L06N_1/VREF_1) ; off-sheet D156
D161: U4.J4(IO_L29N_7) ; off-sheet D161
D162: U4.C4(IO_L01P_7/VRN_7) ; off-sheet D162
D165: U4.A15(IO_L25P_1) ; off-sheet D165
D166: U4.B19(IO_L06P_1) ; off-sheet D166
D171: U4.H2(IO_L28P_7) ; off-sheet D171
D172: U4.C3(IO_L01N_7/VRP_7) ; off-sheet D172
D175: U4.B15(IO_L25N_1) ; off-sheet D175
D176: U4.C19(IO_L01N_1/VRP_1) ; off-sheet D176
DIN0: U4.Y7(IO_L19N_5)
DIN1: U4.AB7(IO_L22N_5)
DIN2: U4.W8(IO_L24N_5)
DIN3: U4.AB8(IO_L25N_5)
DIN4: U4.W9(IO_L27N_5/VREF_5)
DIN5: U4.AB9(IO_L28N_5/D6)
DIN6: U4.Y10(IO_L29N_5)
DIN7: U4.AB10(IO_L30N_5)
DIN8: U4.W11(IO_L31N_5/D4)
DIN9: U4.AA11(IO_L32N_5/GCLK3)
DIP0: U4.W7(IO_L19P_5/VREF_5)
DIP1: U4.AA7(IO_L22P_5)
DIP2: U4.V8(IO_L24P_5)
DIP3: U4.AA8(IO_L25P_5)
DIP4: U4.V9(IO_L27P_5)
DIP5: U4.AA9(IO_L28P_5/D7)
DIP6: U4.W10(IO_L29P_5/VREF_5)
DIP7: U4.AA10(IO_L30P_5)
DIP8: U4.V11(IO_L31P_5/D5)
DIP9: U4.Y11(IO_L32P_5/GCLK2)
NetR5_2: R5.2 U4.AA5(IO_L10P_5/VRN_5)
NetR6_1: R6.1 U4.AB5(IO_L10N_5/VRP_5)

Not connected (* = marked no-connect by the designer): U4 AA3(IO_L01P_5/CS_B) AA4(IO_L06P_5) AA6(IO_L16N_5) AB4(IO_L06N_5) AB11(IO/VREF_5) G1(IO_L27N_7) G2(IO_L27P_7/VREF_7) G4(IO_L26P_7) M17(IO_L38P_3) M18(IO_L38N_3) M19(IO_L39P_3) M20(IO_L39N_3) M21(IO_L40P_3) M22(IO_L40N_3/VREF_3) N17(IO_L33P_3) N18(IO_L33N_3) N19(IO_L34P_3/VREF_3) N20(IO_L34N_3) N21(IO_L35P_3) N22(IO_L35N_3) P17(IO_L31P_3) P18(IO_L31N_3) P19(IO_L29N_3) P21(IO_L32P_3) P22(IO_L32N_3) R18(IO_L24N_3) R19(IO_L29P_3) R21(IO_L28P_3) R22(IO_L28N_3) T17(IO_L22N_3) T18(IO_L24P_3) T19(IO_L26P_3) T20(IO_L26N_3) T21(IO_L27P_3) T22(IO_L27N_3) U6(IO/VREF_5) U7(IO) U9(IO) U10(IO) U11(IO) U18(IO_L22P_3) U19(IO_L20N_3) U20(IO_L23P_3/VREF_3) U21(IO_L23N_3) V6(IO_L15P_5) V7(IO) V10(IO) V19(IO_L17N_3) V20(IO_L20P_3) V21(IO_L21P_3) V22(IO_L21N_3) W5(IO_L09P_5) W6(IO_L15N_5) W19(IO_L17P_3/VREF_3) W20(IO_L19P_3) W21(IO_L19N_3) W22(IO_L16N_3) Y4(IO_L01N_5/RDWR_B) Y5(IO_L09N_5) Y6(IO_L16P_5) Y19(IO_L01P_3/VRN_3) Y20(IO_L01N_3/VRP_3) Y21(IO) Y22(IO_L16P_3)

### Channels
FPGA1: designators R5=R5A R6=R6A U4=U4A#2
FPGA2: designators R5=R5B R6=R6B U4=U4B#2

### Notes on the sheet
- 16 Channel ADC: FPGA 2
- D050361
- 4
- 11
- A
- Daniel Sigg

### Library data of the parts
R5 R6 = Res2: Resistor
U4 = XC3S1500-4FG456C: as U4 on sheet StdADC03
